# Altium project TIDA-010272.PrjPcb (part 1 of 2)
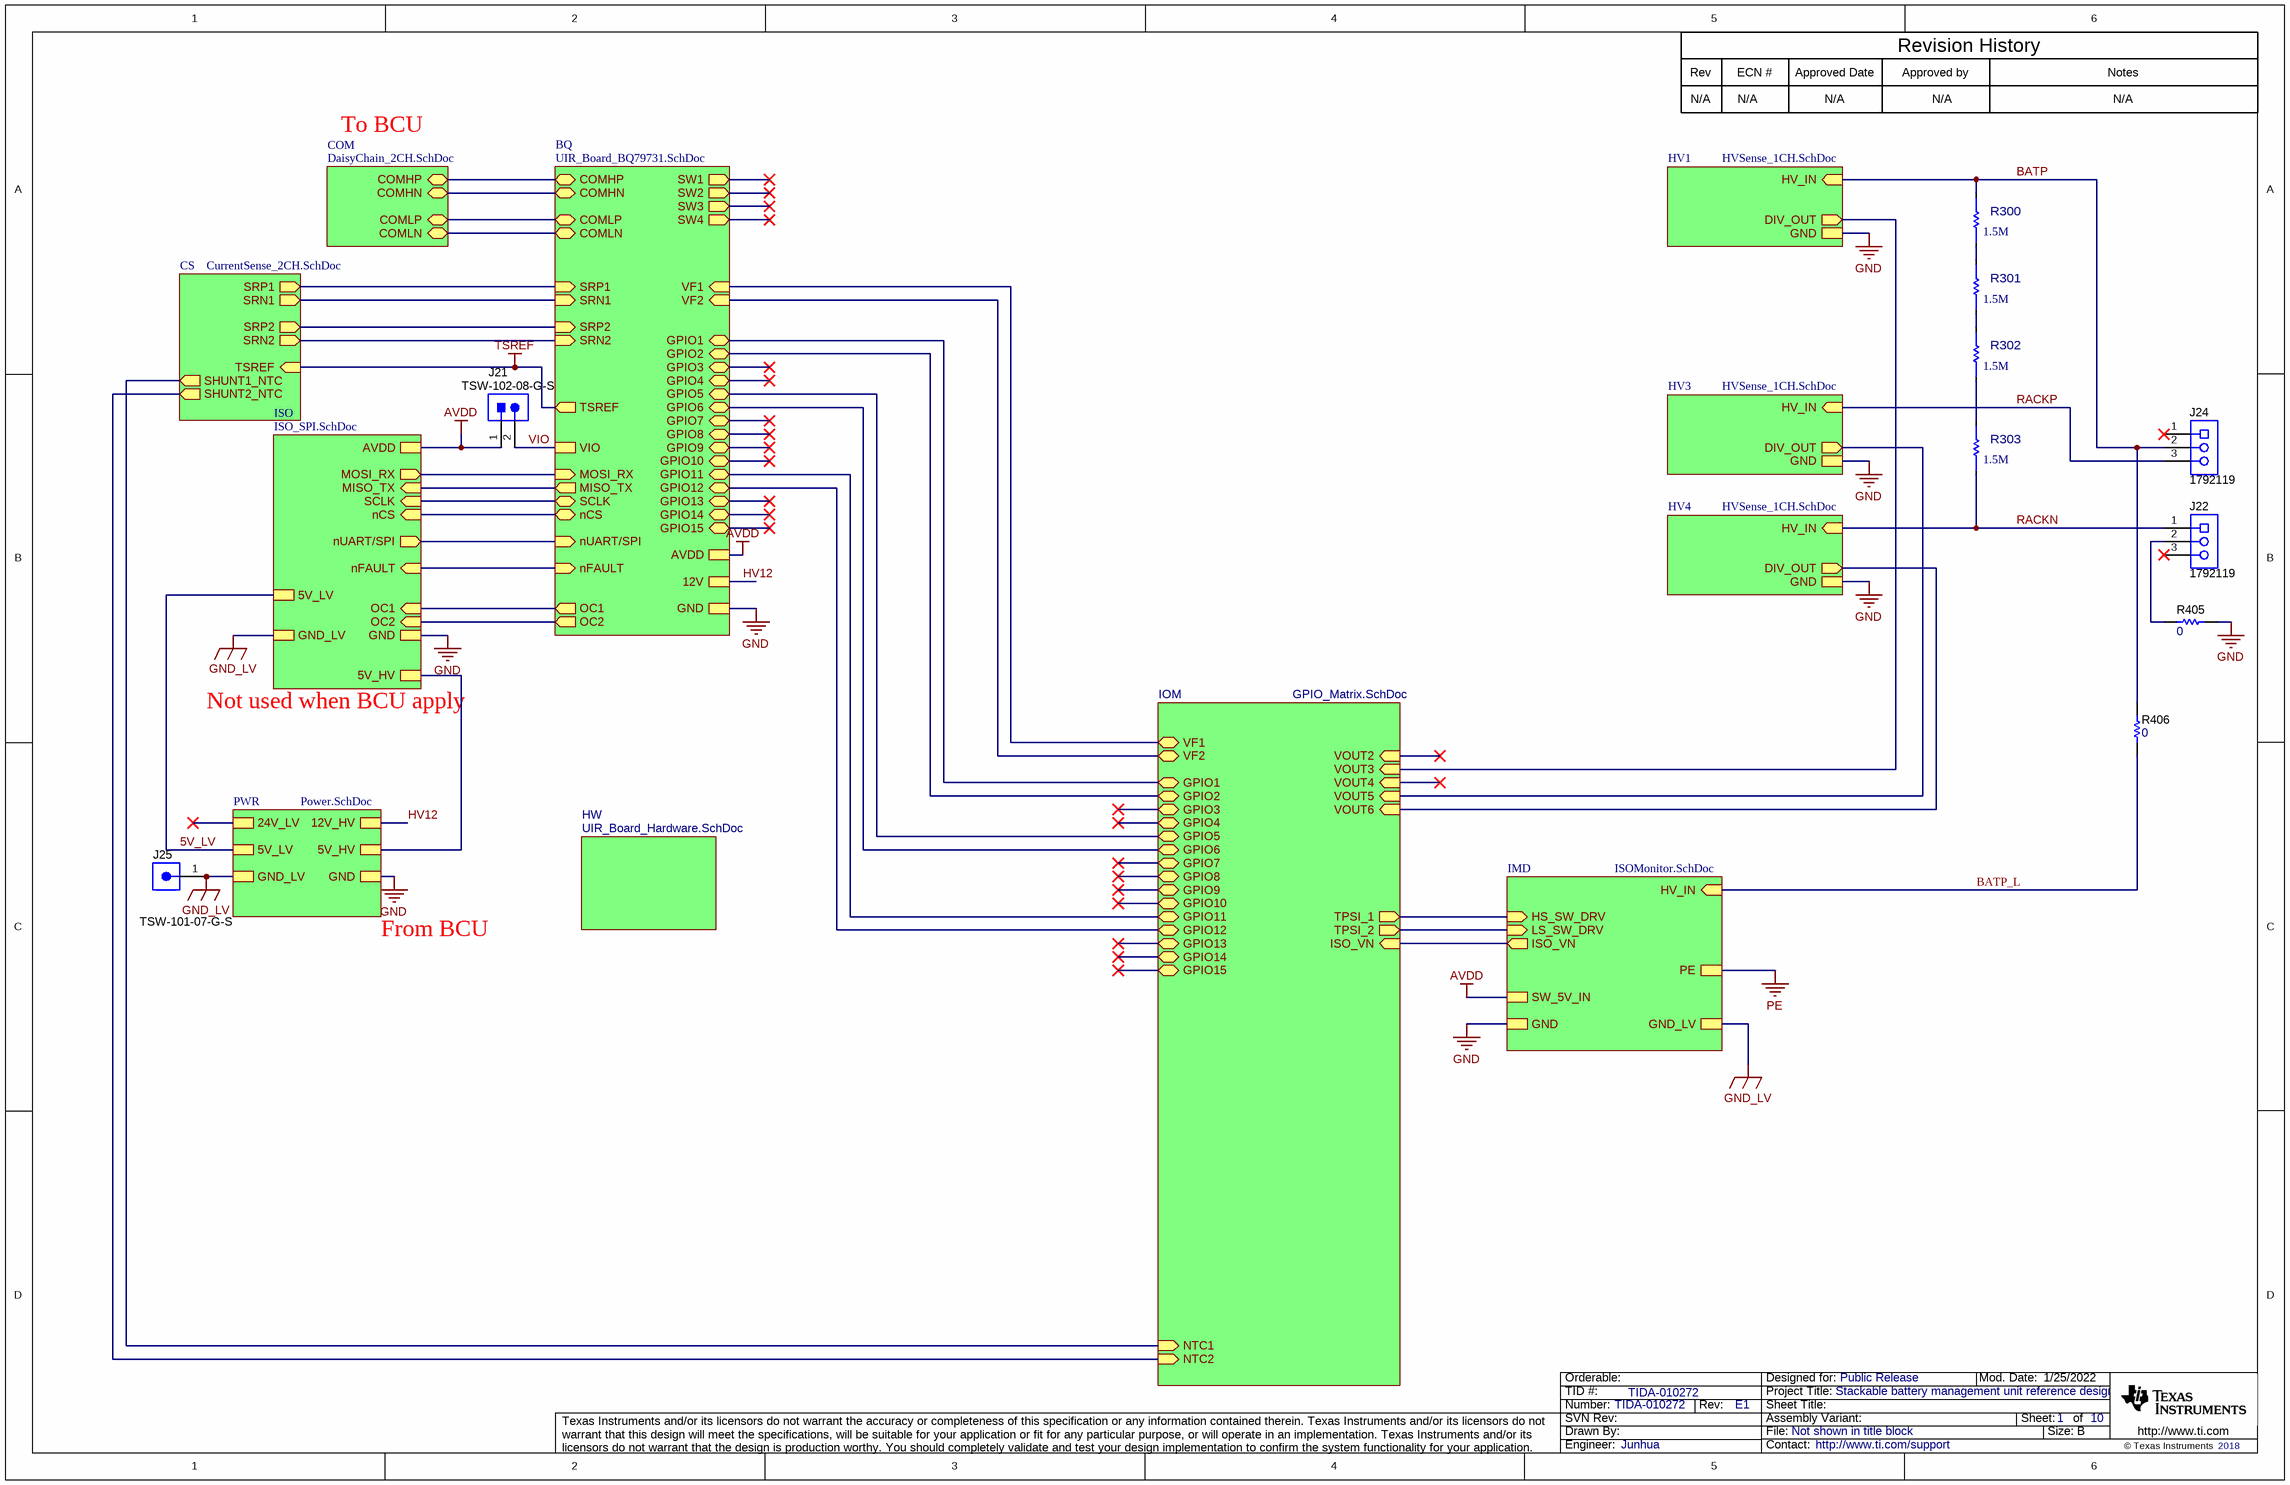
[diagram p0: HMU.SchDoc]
CopyrightYear: 2018; Orderable: N/A; PCB_Layout: Junhua; PCB_Rev: E1; PRJ_Customer: Public Release; PRJ_Engineer: Junhua; PRJ_Number: TIDA-010272; PRJ_Title: Stackable battery management unit reference design; SCH_Rev: E1; TechSupport: http://www.ti.com/support; TID: TIDA-010272
10 sheets, 311 parts. Net scope: hierarchical (ports join the sheet entries above them; power ports are global).
Board file: HMU.PcbDoc
Sheets:
  HMU.SchDoc
    BQ = UIR_Board_BQ79731.SchDoc
    COM = DaisyChain_2CH.SchDoc
    CS = CurrentSense_2CH.SchDoc
    HV1 = HVSense_1CH.SchDoc
    HV3 = HVSense_1CH.SchDoc
    IOM = GPIO_Matrix.SchDoc
    HV4 = HVSense_1CH.SchDoc
    ISO = ISO_SPI.SchDoc
    PWR = Power.SchDoc
    HW = UIR_Board_Hardware.SchDoc
    IMD = ISOMonitor.SchDoc

## Sheet HMU.SchDoc
size 431 x 279 mm; Date: Not shown in title block; ApprovedBy: Not shown in title block; CheckedBy: Not shown in title block; Author: Not shown in title block; CompanyName: Not shown in title block; Engineer: Not shown in title block; Organization: Not shown in title block; Address1: Not shown in title block; Address2: Not shown in title block; Address3: Not shown in title block; Address4: Not shown in title block; DocumentNumber: 1; Revision: Use project parameter SCH_Rev; SheetNumber: 1; SheetTotal: 10; PageSetup: Record=PageOptions¦CenterHorizontal=True¦CenterVertical=True¦PrintScale=1.00¦XCorrection=1.00¦YCorrection=1.00¦PrintKind=0¦BorderSize=5000000¦LeftOffset=0¦BottomOffset=0¦Orientation=2¦PaperLength=1000¦PaperWidth=1000¦Scale=100¦PaperSource=15¦PrintQuality=600¦MediaType=1¦DitherType=10¦PaperKind=Letter¦PrintScaleMode=1

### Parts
J21  TSW-102-08-G-S  [Samtec_TSW-102-08-x-S]
J22  1792119  [Phoenix_1792119]
J24  1792119  [Phoenix_1792119]
J25  TSW-101-07-G-S  [TSW-101-07-G-S]
R300  value 1.5M  [FP-CHV1206-FX-1504ELF_1206-MFG]  (hidden comment: CHV1206-FX-1504ELF)
R301  value 1.5M  [FP-CHV1206-FX-1504ELF_1206-MFG]  (hidden comment: CHV1206-FX-1504ELF)
R302  value 1.5M  [FP-CHV1206-FX-1504ELF_1206-MFG]  (hidden comment: CHV1206-FX-1504ELF)
R303  value 1.5M  [FP-CHV1206-FX-1504ELF_1206-MFG]  (hidden comment: CHV1206-FX-1504ELF)
R405  ValueDisplayed: 0  [0603]  (hidden comment: CRCW06030000Z0EA)
R406  ValueDisplayed: 0  [0603]  (hidden comment: CRCW06030000Z0EA)

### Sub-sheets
BQ = UIR_Board_BQ79731.SchDoc: COMHP (bidir), COMHN (bidir), COMLP (bidir), COMLN (bidir), SW1 (out), SW2 (out), SW3 (out), SW4 (out), OC1 (out), OC2 (out), SRN1 (in), SRN2 (in), SRP1 (in), SRP2 (in), TSREF (out), VIO, MOSI_RX (in), MISO_TX (out), nCS (bidir), SCLK (bidir), nUART/SPI (in), nFAULT (in), VF1 (in), VF2 (in), GPIO1 (bidir), GPIO2 (bidir), GPIO3 (bidir), GPIO4 (bidir), GPIO5 (bidir), GPIO6 (bidir), GPIO7 (bidir), GPIO8 (bidir), GPIO9 (bidir), GPIO10 (bidir), GPIO11 (bidir), GPIO12 (bidir), GPIO13 (bidir), GPIO14 (bidir), GPIO15 (bidir), AVDD, 12V, GND
COM = DaisyChain_2CH.SchDoc: COMHP (bidir), COMHN (bidir), COMLP (bidir), COMLN (bidir)
CS = CurrentSense_2CH.SchDoc: SRN1 (out), SRN2 (out), SRP1 (out), SRP2 (out), SHUNT1_NTC (out), SHUNT2_NTC (out), TSREF (in)
HV1 = HVSense_1CH.SchDoc: HV_IN (in), DIV_OUT (out), GND
HV3 = HVSense_1CH.SchDoc: HV_IN (in), DIV_OUT (out), GND
HV4 = HVSense_1CH.SchDoc: HV_IN (in), DIV_OUT (out), GND
HW = UIR_Board_Hardware.SchDoc: no entries
IMD = ISOMonitor.SchDoc: HV_IN (in), HS_SW_DRV (in), LS_SW_DRV (in), SW_5V_IN, GND_LV, GND, ISO_VN (out), PE
IOM = GPIO_Matrix.SchDoc: GPIO1 (bidir), GPIO2 (bidir), GPIO3 (bidir), GPIO4 (bidir), GPIO5 (bidir), GPIO6 (bidir), GPIO7 (bidir), GPIO8 (bidir), GPIO9 (bidir), GPIO10 (bidir), GPIO11 (bidir), GPIO12 (bidir), GPIO13 (bidir), GPIO14 (bidir), GPIO15 (bidir), VOUT6 (in), VOUT2 (in), VOUT3 (in), VOUT4 (in), VOUT5 (in), ISO_VN (in), TPSI_1 (out), TPSI_2 (out), NTC2 (in), NTC1 (in), VF1 (bidir), VF2 (bidir)
ISO = ISO_SPI.SchDoc: AVDD, MOSI_RX (out), MISO_TX (in), nCS (in), SCLK (in), nUART/SPI (out), nFAULT (in), OC1 (in), OC2 (in), GND, 5V_LV, GND_LV, 5V_HV
PWR = Power.SchDoc: GND_LV, 24V_LV, 12V_HV, 5V_LV, GND, 5V_HV

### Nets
AVDD: J21.1 ; sheet BQ/AVDD, sheet ISO/AVDD, sheet IMD/SW_5V_IN
GND: R405.2 ; sheet BQ/GND, sheet HV1/GND, sheet HV3/GND, sheet HV4/GND, sheet ISO/GND, sheet PWR/GND, sheet IMD/GND
GND_LV: J25.1 ; sheet ISO/GND_LV, sheet PWR/GND_LV, sheet IMD/GND_LV
HV12: sheet BQ/12V, sheet PWR/12V_HV
TSREF: sheet BQ/TSREF, sheet CS/TSREF
VIO: J21.2 ; sheet BQ/VIO
5V_HV: sheet ISO/5V_HV, sheet PWR/5V_HV
5V_LV: sheet ISO/5V_LV, sheet PWR/5V_LV
BATP: J24.2 R300.2 R406.2 ; sheet HV1/HV_IN
BATP_L: R406.1 ; sheet IMD/HV_IN
COMHN: sheet BQ/COMHN, sheet COM/COMHN
COMHP: sheet BQ/COMHP, sheet COM/COMHP
COMLN: sheet BQ/COMLN, sheet COM/COMLN
COMLP: sheet BQ/COMLP, sheet COM/COMLP
DIV_OUT: sheet HV1/DIV_OUT, sheet IOM/VOUT3
DIV_OUT: sheet HV3/DIV_OUT, sheet IOM/VOUT5  [a separate net that carries the same name]
DIV_OUT: sheet IOM/VOUT6, sheet HV4/DIV_OUT  [a separate net that carries the same name]
GPIO1: sheet BQ/GPIO1, sheet IOM/GPIO1
GPIO2: sheet BQ/GPIO2, sheet IOM/GPIO2
GPIO5: sheet BQ/GPIO5, sheet IOM/GPIO5
GPIO6: sheet BQ/GPIO6, sheet IOM/GPIO6
GPIO11: sheet BQ/GPIO11, sheet IOM/GPIO11
GPIO12: sheet BQ/GPIO12, sheet IOM/GPIO12
HS_SW_DRV: sheet IOM/TPSI_1, sheet IMD/HS_SW_DRV
ISO_VN: sheet IOM/ISO_VN, sheet IMD/ISO_VN
LS_SW_DRV: sheet IOM/TPSI_2, sheet IMD/LS_SW_DRV
MISO_TX: sheet BQ/MISO_TX, sheet ISO/MISO_TX
MOSI_RX: sheet BQ/MOSI_RX, sheet ISO/MOSI_RX
nCS: sheet BQ/nCS, sheet ISO/nCS
nFAULT: sheet BQ/nFAULT, sheet ISO/nFAULT
NTC1: sheet CS/SHUNT1_NTC, sheet IOM/NTC1
NTC2: sheet CS/SHUNT2_NTC, sheet IOM/NTC2
nUART/SPI: sheet BQ/nUART/SPI, sheet ISO/nUART/SPI
OC1: sheet BQ/OC1, sheet ISO/OC1
OC2: sheet BQ/OC2, sheet ISO/OC2
RACKN: J22.1 R303.1 ; sheet HV4/HV_IN
RACKP: J24.3 ; sheet HV3/HV_IN
SCLK: sheet BQ/SCLK, sheet ISO/SCLK
SRN1: sheet BQ/SRN1, sheet CS/SRN1
SRN2: sheet BQ/SRN2, sheet CS/SRN2
SRP1: sheet BQ/SRP1, sheet CS/SRP1
SRP2: sheet BQ/SRP2, sheet CS/SRP2
VF1: sheet BQ/VF1, sheet IOM/VF1
VF2: sheet BQ/VF2, sheet IOM/VF2
NetJ22_2: J22.2 R405.1
NetR300_1: R300.1 R301.2
NetR301_1: R301.1 R302.2
NetR302_1: R302.1 R303.2

Not connected (* = marked no-connect by the designer): J22 3*; J24 1*

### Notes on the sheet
- Rev
- N/A
- ECN #
- Approved Date
- Approved by
- Revision History
- Notes
- To BCU
- Not used when BCU apply
- From BCU

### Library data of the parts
J21 = CMP-0077643-1: Header, 2.54mm, 2x1, Gold, TH; Manufacturer: Samtec; Pitch_mm: 2.54; Gender: Male; Cert_CSA: Y; Current_A: 5.7A; Voltage_V: 550V; Row_Count: 1
J22 J24 = CMP-0055525-1: Terminal Block, 7.5mm, 3x1, R/A, TH; Manufacturer: Phoenix Contact; Cert_VDE: Y; CNHeader: FALSE; Current_A: 41A; Gender: Female; Voltage_V: 1kV; Row_Count: 1; Pitch_mm: 7.5; CT: TRUE
J25 = CMP-0075403-1: Header, 100mil, 1pos, Gold, TH; Manufacturer: Samtec; Pitch_mm: 2.54; Cert_VDE: N; Gender: Male; Cert_CSA: Y; Voltage_V: 550V; Green_REACh: Passed; Current_A: 6.3A; CT: False; Green_Lifecycle: Active; Row_Count: 1; CNHeader: True
R300-R303 = CMP-0120473-1: Thick Film High Voltage Chip Resistors 1206 1.5MOhm ±1% ±100ppm/°C; Manufacturer: Bourns; AEC Qualified: No; Power_W: 250mW; SizeZ_mm: 0.65mm; VDC_V: 800V
R405 R406 = CMP-0025697-4: RES, 0, 5%, 0.1 W, AEC-Q200 Grade 0, 0603; Manufacturer: Vishay-Dale; Power_W: 100mW; TempCo: 200 ppm/C; Value_Code: 0000; Value: 0; EIA_Code: E24; SizeX_mm: 1.6; SizeY_mm: 0.8; SizeZ_mm: 1; Value2: 0.1W; SizeArea_mm2: 1.28; AEC Qualified: Y; VDC_V: 75V; AEC Category: Q200

## Sheet UIR_Board_BQ79731.SchDoc
size 431 x 279 mm; SheetNumber: 7; SheetTotal: 10
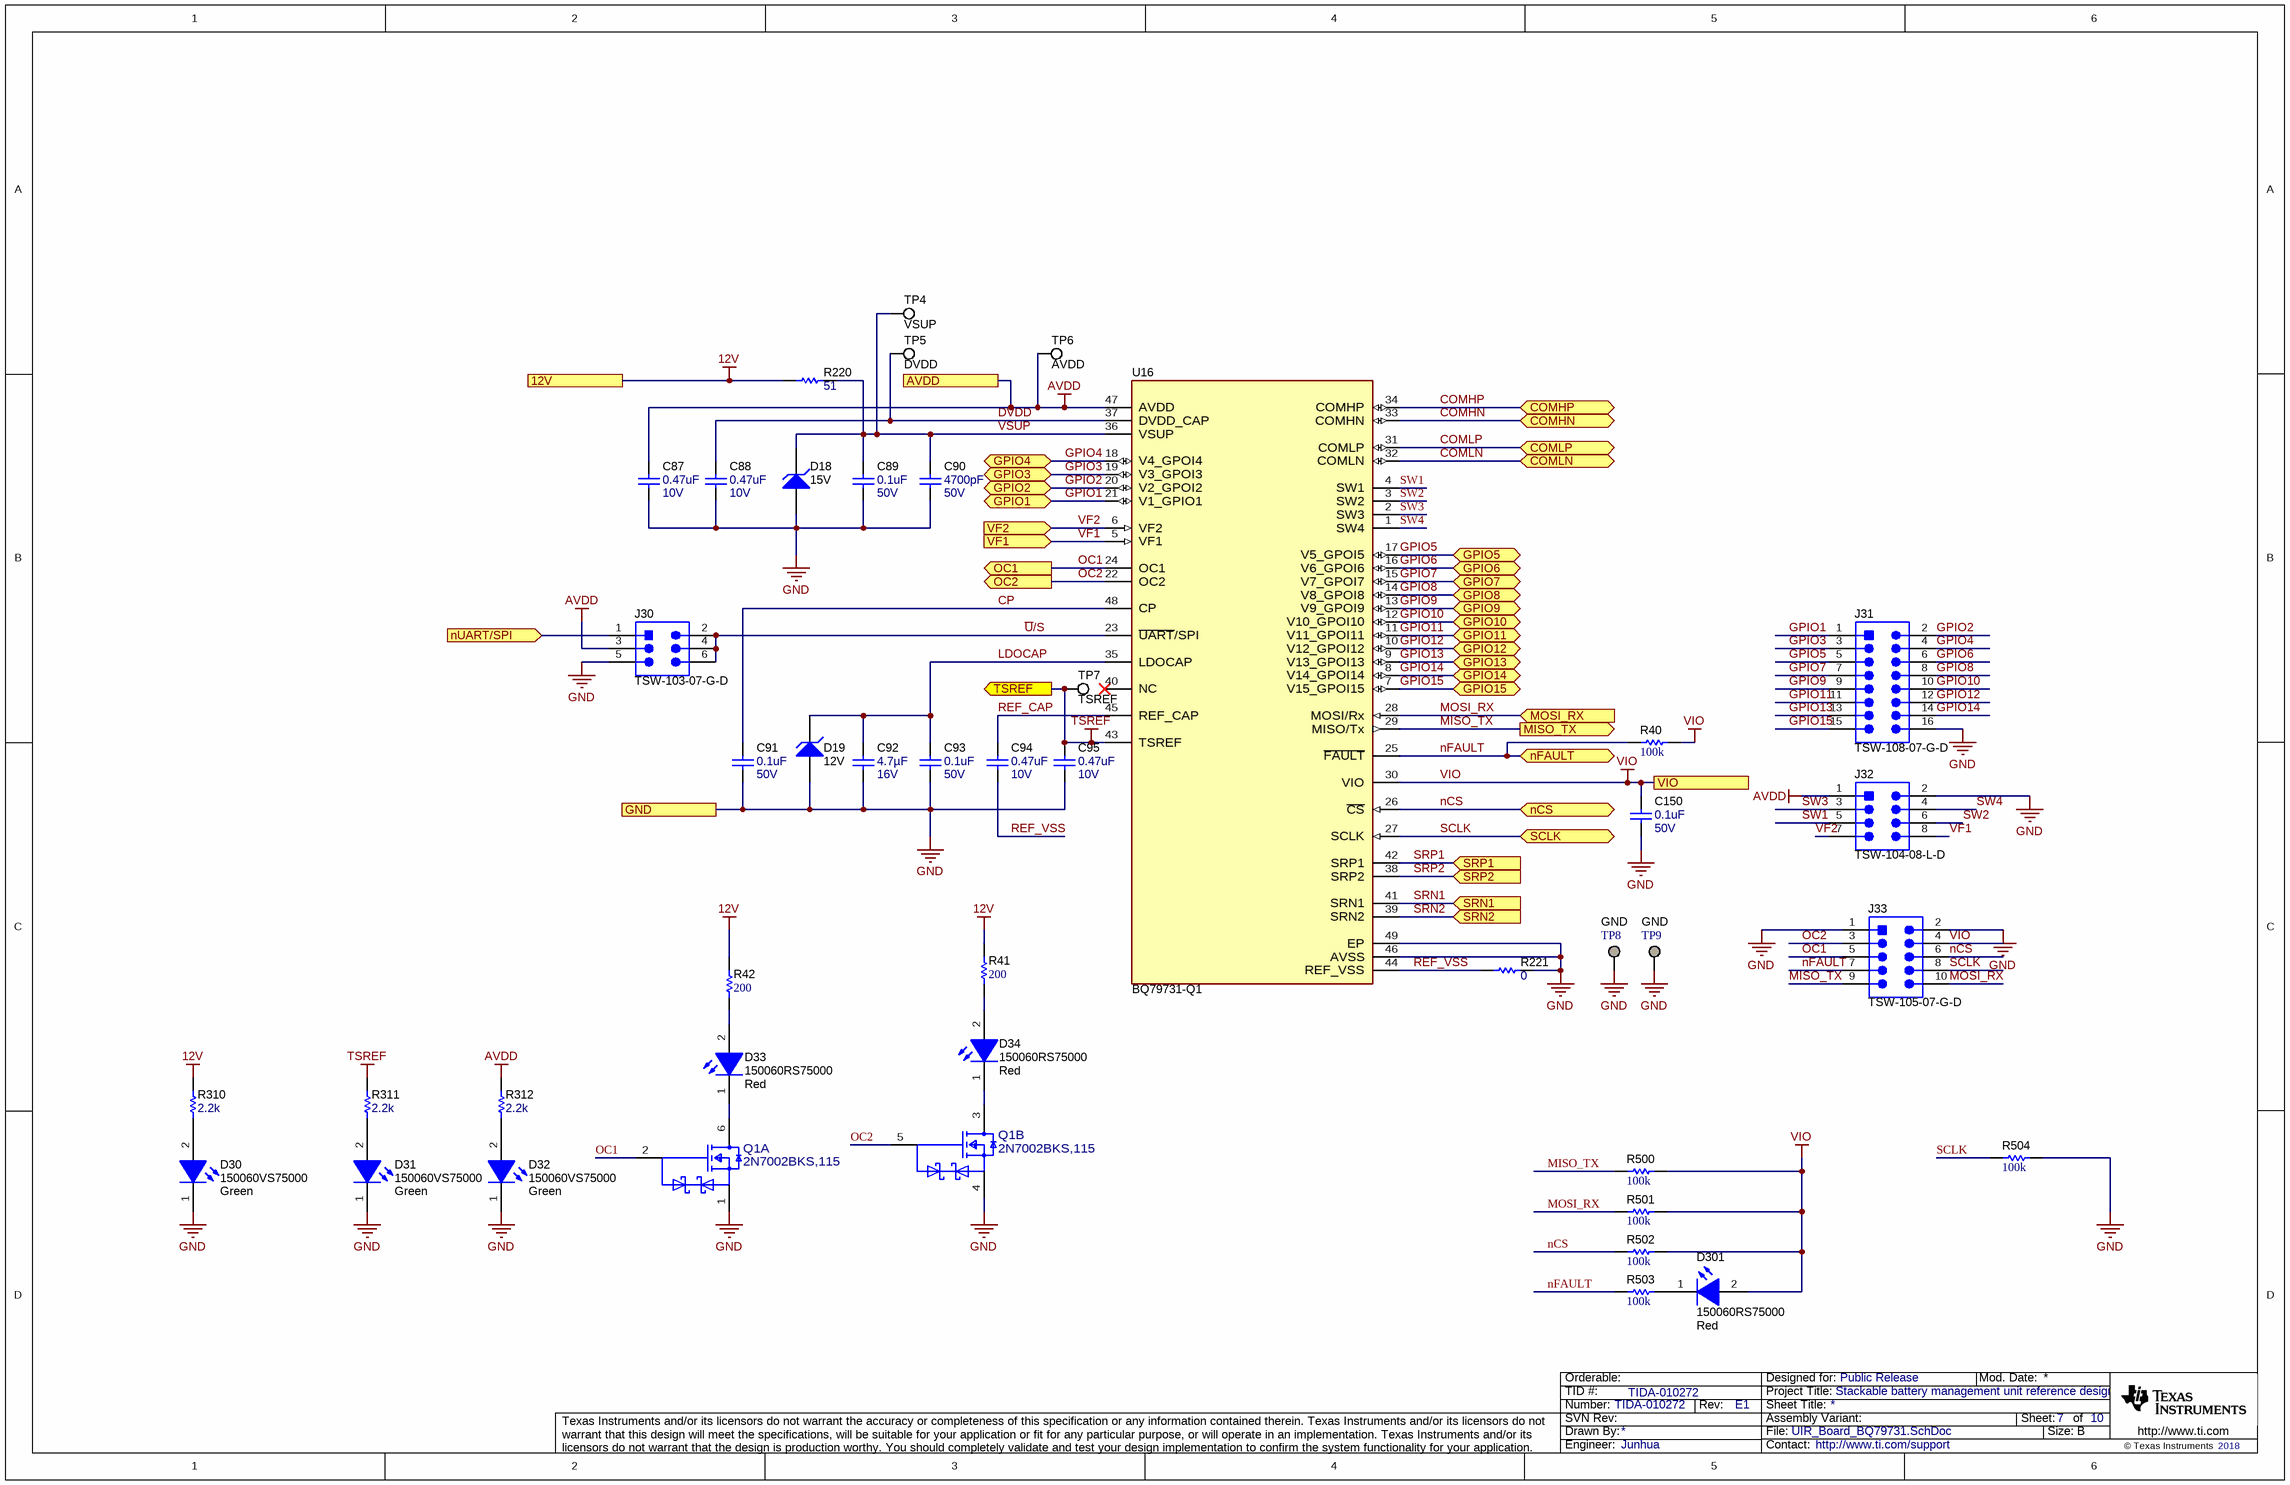
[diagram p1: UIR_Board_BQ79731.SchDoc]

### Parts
C87  VDC_V: 10V  ValueDisplayed: 0.47uF  [0402]  (hidden comment: GRM155R61A474KE15D)
C88  VDC_V: 10V  ValueDisplayed: 0.47uF  [0402]  (hidden comment: GRM155R61A474KE15D)
C89  VDC_V: 50V  ValueDisplayed: 0.1uF  [0402]  (hidden comment: GCM155R71H104KE02D)
C90  VDC_V: 50V  ValueDisplayed: 4700pF  [0402]  (hidden comment: GCM155R71H472KA37D)
C91  VDC_V: 50V  ValueDisplayed: 0.1uF  [0402]  (hidden comment: GCM155R71H104KE02D)
C92  VDC_V: 16V  ValueDisplayed: 4.7µF  [0603]  (hidden comment: GRT188R61C475KE13D)
C93  VDC_V: 50V  ValueDisplayed: 0.1uF  [0402]  (hidden comment: GCM155R71H104KE02D)
C94  VDC_V: 10V  ValueDisplayed: 0.47uF  [0402]  (hidden comment: GRM155R61A474KE15D)
C95  VDC_V: 10V  ValueDisplayed: 0.47uF  [0402]  (hidden comment: GRM155R61A474KE15D)
C150  VDC_V: 50V  ValueDisplayed: 0.1uF  [0402]  (hidden comment: GCM155R71H104KE02D)
D18  value 15V  [SOD-123]  (hidden comment: MMSZ4702-HE3-08)
D19  value 12V  [SOD-123]  (hidden comment: BZT52B12-E3-08)
D30  150060VS75000  value Green  [WL-SMCW_GREEN]
D31  150060VS75000  value Green  [WL-SMCW_GREEN]
D32  150060VS75000  value Green  [WL-SMCW_GREEN]
D33  150060RS75000  value Red  [WL-SMCW_RED]
D34  150060RS75000  value Red  [WL-SMCW_RED]
D301  150060RS75000  value Red  [WL-SMCW_RED]
J30  TSW-103-07-G-D  [TSW-103-07-G-D]
J31  TSW-108-07-G-D  [TSW-108-07-G-D]
J32  TSW-104-08-L-D  [Samtec_TSW-104-08-x-D]
J33  TSW-105-07-G-D  [TSW-105-07-G-D]
Q1  2N7002BKS,115  [FP-2N7002BKS,115_SOT363-MFG]  (parts A,B of 2)
R40  ValueDisplayed: 100k  [0603]  (hidden comment: CRCW0603100KJNEA)
R41  ValueDisplayed: 200  [0603]  (hidden comment: RT0603DRE07200RL)
R42  ValueDisplayed: 200  [0603]  (hidden comment: RT0603DRE07200RL)
R220  ValueDisplayed: 51  [0805_HV]  (hidden comment: CRCW080551R0JNEA)
R221  ValueDisplayed: 0  [0402]  (hidden comment: CRCW04020000Z0ED)
R310  ValueDisplayed: 2.2k  [0603]  (hidden comment: CRCW06032K20JNEA)
R311  ValueDisplayed: 2.2k  [0603]  (hidden comment: CRCW06032K20JNEA)
R312  ValueDisplayed: 2.2k  [0603]  (hidden comment: CRCW06032K20JNEA)
R500  ValueDisplayed: 100k  [0603]  (hidden comment: CRCW0603100KJNEA)
R501  ValueDisplayed: 100k  [0603]  (hidden comment: CRCW0603100KJNEA)
R502  ValueDisplayed: 100k  [0603]  (hidden comment: CRCW0603100KJNEA)
R503  ValueDisplayed: 100k  [0603]  (hidden comment: CRCW0603100KJNEA)
R504  ValueDisplayed: 100k  [0603]  (hidden comment: CRCW0603100KJNEA)
TP4  VSUP  [Keystone5012]
TP5  DVDD  [Keystone5012]
TP6  AVDD  [Keystone5012]
TP7  TSREF  [Keystone5012]
TP8  GND  [Keystone1598-2]
TP9  GND  [Keystone1598-2]
U16  BQ79731-Q1  [PHP0048E-MFG]

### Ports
12V, AVDD, COMHN (bidir), COMHP (bidir), COMLN (bidir), COMLP (bidir), GND, GPIO1 (bidir), GPIO2 (bidir), GPIO3 (bidir), GPIO4 (bidir), GPIO5 (bidir), GPIO6 (bidir), GPIO7 (bidir), GPIO8 (bidir), GPIO9 (bidir), GPIO10 (bidir), GPIO11 (bidir), GPIO12 (bidir), GPIO13 (bidir), GPIO14 (bidir), GPIO15 (bidir), MISO_TX (out), MOSI_RX (in), nCS (bidir), nFAULT (bidir), nUART/SPI (in), OC1 (out), OC2 (out), SCLK (bidir), SRN1 (in), SRN2 (in), SRP1 (in), SRP2 (in), TSREF (out), VF1 (in), VF2 (in), VIO

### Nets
12V: R41.2 R42.2 R220.1 R310.2 ; port 12V  [project net HV12]
AVDD: C87.1 J30.3 J32.1 R312.2 TP6.1 U16.47(AVDD) ; port AVDD
GND: C87.2 C88.2 C89.2 C90.2 C91.2 C92.2 C93.2 C95.2 C150.2 D18.2(A) D19.2(A) D30.1(K) D31.1(K) D32.1(K) J30.5 J31.16 J32.2 J33.1 J33.2 Q1.1(S1) Q1.4(S2) R221.2 R504.2 TP8.1 TP9.1 U16.46(AVSS) U16.49(EP) ; port GND
TSREF: C95.1 R311.2 TP7.1 U16.43(TSREF) ; port TSREF
VIO: C150.1 D301.2(A) J33.4 R40.1 R500.2 R501.2 R502.2 U16.30(VIO) ; port VIO
COMHN: U16.33(COMHN) ; port COMHN
COMHP: U16.34(COMHP) ; port COMHP
COMLN: U16.32(COMLN) ; port COMLN
COMLP: U16.31(COMLP) ; port COMLP
CP: C91.1 U16.48(CP)
DVDD: C88.1 TP5.1 U16.37(DVDD_CAP)
GPIO1: J31.1 U16.21(V1_GPIO1) ; port GPIO1
GPIO2: J31.2 U16.20(V2_GPOI2) ; port GPIO2
GPIO3: J31.3 U16.19(V3_GPOI3) ; port GPIO3
GPIO4: J31.4 U16.18(V4_GPOI4) ; port GPIO4
GPIO5: J31.5 U16.17(V5_GPOI5) ; port GPIO5
GPIO6: J31.6 U16.16(V6_GPOI6) ; port GPIO6
GPIO7: J31.7 U16.15(V7_GPOI7) ; port GPIO7
GPIO8: J31.8 U16.14(V8_GPOI8) ; port GPIO8
GPIO9: J31.9 U16.13(V9_GPOI9) ; port GPIO9
GPIO10: J31.10 U16.12(V10_GPOI10) ; port GPIO10
GPIO11: J31.11 U16.11(V11_GPOI11) ; port GPIO11
GPIO12: J31.12 U16.10(V12_GPOI12) ; port GPIO12
GPIO13: J31.13 U16.9(V13_GPOI13) ; port GPIO13
GPIO14: J31.14 U16.8(V14_GPOI14) ; port GPIO14
GPIO15: J31.15 U16.7(V15_GPOI15) ; port GPIO15
LDOCAP: C92.1 C93.1 D19.1(K) U16.35(LDOCAP)
MISO_TX: J33.9 R500.1 U16.29(MISO/Tx) ; port MISO_TX
MOSI_RX: J33.10 R501.1 U16.28(MOSI/Rx) ; port MOSI_RX
nCS: J33.6 R502.1 U16.26(~{CS}) ; port nCS
nFAULT: J33.7 R40.2 R503.1 U16.25(~{FAULT}) ; port nFAULT
nUART/SPI: J30.1 ; port nUART/SPI
OC1: J33.5 Q1.2(G1) U16.24(OC1) ; port OC1
OC2: J33.3 Q1.5(G2) U16.22(OC2) ; port OC2
REF_CAP: C94.1 U16.45(REF_CAP)
REF_VSS: C94.2 R221.1 U16.44(REF_VSS)
SCLK: J33.8 R504.1 U16.27(SCLK) ; port SCLK
SRN1: U16.41(SRN1) ; port SRN1
SRN2: U16.39(SRN2) ; port SRN2
SRP1: U16.42(SRP1) ; port SRP1
SRP2: U16.38(SRP2) ; port SRP2
SW1: J32.5 U16.4(SW1)
SW2: J32.6 U16.3(SW2)
SW3: J32.3 U16.2(SW3)
SW4: J32.4 U16.1(SW4)
~{U}/S: J30.2 J30.4 J30.6 U16.23(~{UART}/SPI)
VF1: J32.8 U16.5(VF1) ; port VF1
VF2: J32.7 U16.6(VF2) ; port VF2
VSUP: C89.1 C90.1 D18.1(K) R220.2 TP4.1 U16.36(VSUP)
NetD30_2: D30.2(A) R310.1
NetD31_2: D31.2(A) R311.1
NetD32_2: D32.2(A) R312.1
NetD33_1: D33.1(K) Q1.6(D1)
NetD33_2: D33.2(A) R42.1
NetD34_1: D34.1(K) Q1.3(D2)
NetD34_2: D34.2(A) R41.1
NetD301_1: D301.1(K) R503.2

Not connected (* = marked no-connect by the designer): U16 40(NC)*

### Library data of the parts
C87 C88 C94 C95 = CMP-0006580-2: CAP, CERM, 0.47 uF, 10 V, +/- 10%, X5R, 0402; Manufacturer: MuRata; TaMin_C: -55°C; Polarized: N; SizeAreaWB_mm2: 3; Value1: Unknown; U/M: EA; Value: 0.47uF; TaMax_C: 85°C; SizeZ_mm: 0.6; SizeX_mm: 1; SizeY_mm: 0.5; Cap_F: 470nF; AEC Category: Q200
C89 C91 C93 C150 = CMP-0006356-2: CAP, CERM, 0.1 uF, 50 V, +/- 10%, X7R, AEC-Q200 Grade 1, 0402; Manufacturer: MuRata; TaMin_C: -55°C; Polarized: N; SizeAreaWB_mm2: 3; Value1: Unknown; U/M: EA; Value: 0.1uF; TaMax_C: 125°C; SizeZ_mm: 0.6; SizeX_mm: 1; SizeY_mm: 0.5; AEC Qualified: Y; Cap_F: 100nF; AEC Category: Q200
C90 = CMP-0006361-2: CAP, CERM, 4700 pF, 50 V, +/- 10%, X7R, AEC-Q200 Grade 1, 0402; Manufacturer: MuRata; TaMin_C: -55°C; Polarized: N; SizeAreaWB_mm2: 3; Value1: Unknown; U/M: EA; Value: 4700pF; TaMax_C: 125°C; SizeZ_mm: 0.6; SizeX_mm: 1; SizeY_mm: 0.5; AEC Qualified: Y; Cap_F: 4.7nF; AEC Category: Q200
C92 = CMP-0081052-1: CAP, CERM, 4.7 µF, 16 V,+/- 10%, X5R, AEC-Q200 Grade 3, 0603; Manufacturer: MuRata; SizeAreaWB_mm2: 4.68; SizeArea_mm2: 1.28; AEC Qualified: Y; AEC Category: Q200; Value: 4.7uF; TaMax_C: 85°C; SizeZ_mm: 1; AEC Grade: 3; Polarized: N; TaMin_C: -55°C; SizeY_mm: 0.8; U/M: EA; SizeX_mm: 1.6
D18 = CMP-0077575-3: Diode, Zener, 15 V, 500 mW, AEC-Q101, SOD-123; Manufacturer: Vishay-Semiconductor; SizeAreaWB_mm2: 13.095; Power_W: 500mW; AEC Category: Q101; SizeX_mm: 3.85; Value1: 0.5W; SizeZ_mm: 1.35; AEC Qualified: Y; SizeY_mm: 1.7; SizeArea_mm2: 6.545; RJA_CperW: 340
D19 = CMP-0005773-4: Diode, Zener, 12 V, 500 mW, AEC-Q101, SOD-123; Manufacturer: Vishay-Semiconductor; SizeX_mm: 3.85; RJA_CperW: 300; SizeY_mm: 1.7; AEC Qualified: Y; SizeZ_mm: 1.35; Power_W: 500mW; AEC Category: Q101; SizeAreaWB_mm2: 13.095; Value1: 0.5W; SizeArea_mm2: 6.545
D30-D32 = CMP-0002894-2: LED, Green, SMD; Manufacturer: Wurth Elektronik; Type: AlInGaP; Value2: 2V; Io_A: 20mA; Value1: W
D33 D34 D301 = CMP-0002947-3: LED, Red, SMD; Manufacturer: Wurth Elektronik; Value1: 0.072W; Vf_V: 2V; Angle: 140; Tjmax_C: 85°C; Type: AlInGaP; Vr_V: 5V; Io_A: 30mA; Power_TotalModule: 72mW
J30 = CMP-0075406-2: Header, 100mil, 3x2, Gold, TH; Manufacturer: Samtec; Pitch_mm: 2.54; Cert_VDE: N; Gender: Male; Cert_CSA: Y; Voltage_V: 550V; Green_REACh: Passed; Current_A: 6.3A; Green_Lifecycle: Active; Row_Count: 2
J31 = CMP-0075418-1: Header, 100mil, 8x2, Gold, TH; Manufacturer: Samtec; Pitch_mm: 2.54; Cert_VDE: N; Gender: Male; Cert_CSA: Y; Voltage_V: 550V; Green_REACh: Passed; Current_A: 6.3A; CT: False; Green_Lifecycle: Active; Row_Count: 2; CNHeader: True
J32 = CMP-0055596-2: Header, 2.54mm, 4x2, Gold, TH; Manufacturer: Samtec; Current_A: 6.3A; Shrouded: N; Gender: Male; Cert_CSA: Y; Voltage_V: 550V; Row_Count: 2; RowSpacing_mm: 2.54
J33 = CMP-0075410-2: Header, 100mil, 5x2, Gold, TH; Manufacturer: Samtec; Pitch_mm: 2.54; Cert_VDE: N; Gender: Male; Cert_CSA: Y; Voltage_V: 550V; Green_REACh: Passed; Current_A: 6.3A; Green_Lifecycle: Active; Row_Count: 2
Q1 = CMP-0089965-1: Mosfet Array 2 N-Channel (Dual) 60V 300mA 295mW Surface Mount 6-TSSOP; Manufacturer: Nexperia; Pulse Drain Current: 1.2A; Vgs_V: 20V; Typ Forward Diode Voltage: 0.75V; AEC Grade: Grade 0; Rdson45_ohm: 1; Threshold Vgs Max: 2.1V; QgTyp_nC: 0.5nC @ 4.5V; Rthja Max: 370K/W; VdsMax_V: 1.1V; TJmax_C: +150°C; AEC Qualified: Yes; Turn On Delay Time: 5ns; Number Of Channels: 2; ChMode: False; TaMin_C: -55°C; Input Capacitace At Vds: 33pF @ 10V; Turn Off Delay Time: 12ns; SizeZ_mm: 1.1mm; Transconductance: 0.55S
R40 R500-R504 = CMP-0025698-4: RES, 100 k, 5%, 0.1 W, AEC-Q200 Grade 0, 0603; Manufacturer: Vishay-Dale; Power_W: 100mW; TempCo: 200 ppm/C; Value: 100k; EIA_Code: E24; SizeX_mm: 1.6; SizeY_mm: 0.8; SizeZ_mm: 1; Value2: 0.1W; SizeArea_mm2: 1.28; AEC Qualified: Y; VDC_V: 75V; AEC Category: Q200; AEC Grade: 0
R41 R42 = CMP-0024912-2: RES, 200, 0.5%, 0.1 W, 0603; Manufacturer: Yageo America; Power_W: 100mW; TempCo: 50 ppm/C; Value_Code: 200R; U/M: EA; Value: 200; EIA_Code: E192; SizeX_mm: 1.6; SizeY_mm: 0.8; SizeZ_mm: 1; Value2: 0.1W; SizeArea_mm2: 1.28; VDC_V: 75V; AEC Category: Q200
R220 = CMP-0020567-3: RES, 51, 5%, 0.125 W, AEC-Q200 Grade 0, 0805; Manufacturer: Vishay-Dale; Power_W: 125mW; TempCo: 200 ppm/C; Value_Code: 51R0; Value: 51; EIA_Code: E24; SizeX_mm: 2; SizeY_mm: 1.25; SizeZ_mm: 1.45; Value2: 0.125W; SizeArea_mm2: 2.5; AEC Qualified: Y; VDC_V: 150V; AEC Category: Q200; AEC Grade: 0
R221 = CMP-0026822-3: RES, 0, 5%, 0.063 W, AEC-Q200 Grade 0, 0402; Manufacturer: Vishay-Dale; Power_W: 63mW; TempCo: 200 ppm/C; Value_Code: 0000; Value: 0; EIA_Code: E24; SizeX_mm: 1; SizeY_mm: 0.5; SizeZ_mm: 0.6; Value2: 0.063W; AEC Qualified: Y; VDC_V: 50V; AEC Category: Q200
R310-R312 = CMP-0025769-4: RES, 2.2 k, 5%, 0.1 W, AEC-Q200 Grade 0, 0603; Manufacturer: Vishay-Dale; Power_W: 100mW; TempCo: 200 ppm/C; Value_Code: 2k20; Value: 2.2k; EIA_Code: E24; SizeX_mm: 1.6; SizeY_mm: 0.8; SizeZ_mm: 1; Value2: 0.1W; SizeArea_mm2: 1.28; AEC Qualified: Y; VDC_V: 75V; AEC Category: Q200; AEC Grade: 0
TP4-TP7 = CMP-0055149-1: Test Point, Multipurpose, White, TH; PartNumber: 5012; Manufacturer: Keystone; ContactFinish: Silver; CNHeader: FALSE; Green_Lifecycle: Active; Green_REACh: Passed; CT: TRUE
TP8 TP9 = CMP-0055121-1: Terminal, Turret, TH, Triple; Manufacturer: Keystone; PartNumber: 1598-2; CT: FALSE; Green_REACh: Passed; CompType: Turret Terminal; Green_Lifecycle: Active
U16 = CMP-0093215-2: Functional Safety-Compliant Automotive UIR sensor for Battery Junction Box (BJB) and other High Voltge and Current sensing; Manufacturer: Texas Instruments; Number Of Outputs: 4; Nominal Supply Current: 10mA; AEC Category: Q200; TaMin_C: -40°C; AEC Qualified: Yes; Min Supply Voltage: 6V; AEC Grade: Grade 1; Max Supply Voltage: 18V; CompType: IC; TaMax_C: +125°C; Standoff Height: 0.05mm; SizeZ_mm: 1.2mm; TJmax_C: +150°C

## Sheet DaisyChain_2CH.SchDoc
size 431 x 279 mm; SheetNumber: 5; SheetTotal: 10
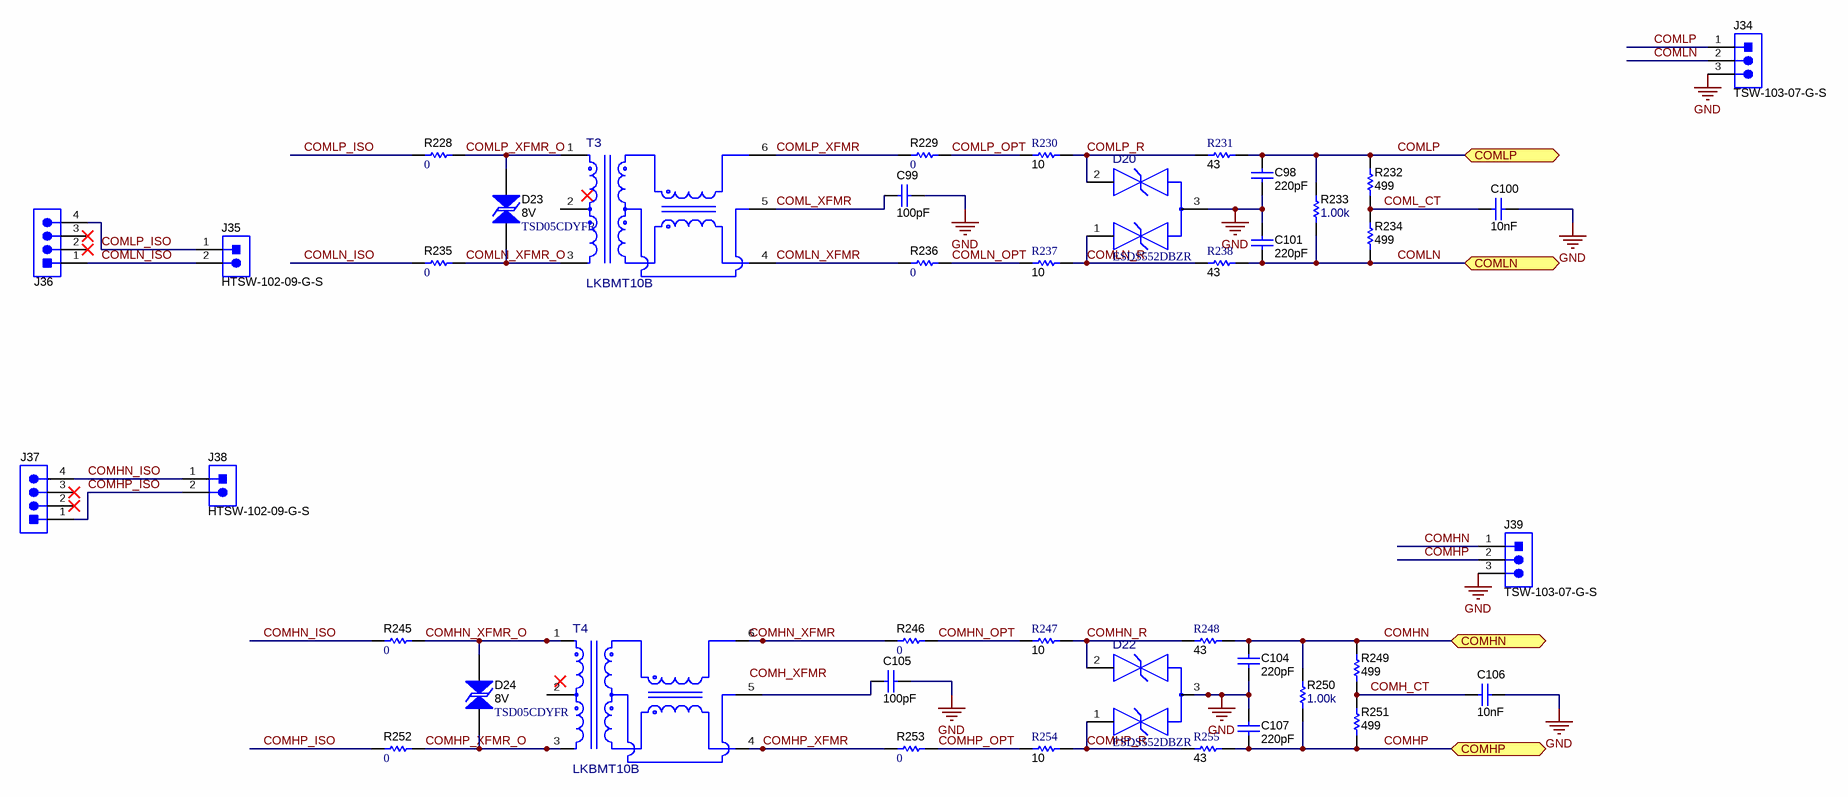
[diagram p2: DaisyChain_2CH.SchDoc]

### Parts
C98  Cap_F: 220pF  [0603]  (hidden comment: CL10B221JB8NNNC)
C99  ValueDisplayed: 100pF  [0603]  (hidden comment: GCM1885C1H101JA16J)
C100  Cap_F: 10nF  [0603]  (hidden comment: CL10B103KB8NCNC)
C101  Cap_F: 220pF  [0603]  (hidden comment: CL10B221JB8NNNC)
C104  Cap_F: 220pF  [0603]  (hidden comment: CL10B221JB8NNNC)
C105  ValueDisplayed: 100pF  [0603]  (hidden comment: GCM1885C1H101JA16J)
C106  Cap_F: 10nF  [0603]  (hidden comment: CL10B103KB8NCNC)
C107  Cap_F: 220pF  [0603]  (hidden comment: CL10B221JB8NNNC)
D20  ESDS552DBZR  [DBZ0003A-MFG]
D22  ESDS552DBZR  [DBZ0003A-MFG]
D23  value 8V  PartNumber: TSD05CDYFR  [SOD-323-Bi]  (hidden comment: CDSOD323-T08SC)
D24  value 8V  PartNumber: TSD05CDYFR  [SOD-323-Bi]  (hidden comment: CDSOD323-T08SC)
J34  TSW-103-07-G-S  [TSW-103-07-G-S]
J35  HTSW-102-09-G-S  [Samtec_HTSW-102-09-x-S]
J36  70551-0038  [Molex_70551-0038]  (value not drawn)
J37  70551-0038  [Molex_70551-0038]  (value not drawn)
J38  HTSW-102-09-G-S  [Samtec_HTSW-102-09-x-S]
J39  TSW-103-07-G-S  [TSW-103-07-G-S]
R228  ValueDisplayed: 0  [0603]  (hidden comment: RC0603JR-070RL)
R229  ValueDisplayed: 0  [0603]  (hidden comment: RC0603JR-070RL)
R230  ValueDisplayed: 10  [0603]  (hidden comment: CRCW060310R0JNEA)
R231  ValueDisplayed: 43  [0603]  (hidden comment: CRCW060343R0JNEA)
R232  ValueDisplayed: 499  [0603]  (hidden comment: RC0603FR-07499RL)
R233  ValueDisplayed: 1.00k  [0603]  (hidden comment: CRCW06031K00FKEA)
R234  ValueDisplayed: 499  [0603]  (hidden comment: RC0603FR-07499RL)
R235  ValueDisplayed: 0  [0603]  (hidden comment: RC0603JR-070RL)
R236  ValueDisplayed: 0  [0603]  (hidden comment: RC0603JR-070RL)
R237  ValueDisplayed: 10  [0603]  (hidden comment: CRCW060310R0JNEA)
R238  ValueDisplayed: 43  [0603]  (hidden comment: CRCW060343R0JNEA)
R245  ValueDisplayed: 0  [0603]  (hidden comment: RC0603JR-070RL)
R246  ValueDisplayed: 0  [0603]  (hidden comment: RC0603JR-070RL)
R247  ValueDisplayed: 10  [0603]  (hidden comment: CRCW060310R0JNEA)
R248  ValueDisplayed: 43  [0603]  (hidden comment: CRCW060343R0JNEA)
R249  ValueDisplayed: 499  [0603]  (hidden comment: RC0603FR-07499RL)
R250  ValueDisplayed: 1.00k  [0603]  (hidden comment: CRCW06031K00FKEA)
R251  ValueDisplayed: 499  [0603]  (hidden comment: RC0603FR-07499RL)
R252  ValueDisplayed: 0  [0603]  (hidden comment: RC0603JR-070RL)
R253  ValueDisplayed: 0  [0603]  (hidden comment: RC0603JR-070RL)
R254  ValueDisplayed: 10  [0603]  (hidden comment: CRCW060310R0JNEA)
R255  ValueDisplayed: 43  [0603]  (hidden comment: CRCW060343R0JNEA)
T3  LKBMT10B  [FP-LKBMT10B_SMT_XFRMR_27MM9_12MM5-MFG]
T4  LKBMT10B  [FP-LKBMT10B_SMT_XFRMR_27MM9_12MM5-MFG]

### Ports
COMHN (bidir), COMHP (bidir), COMLN (bidir), COMLP (bidir)

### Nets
GND: C98.2 C99.2 C100.1 C101.1 C104.2 C105.2 C106.1 C107.1 D20.3(GND) D22.3(GND) J34.3 J39.3
COMH_CT: C106.2 R249.1 R251.2
COMHN: C104.1 J39.1 R248.2 R249.2 R250.2 ; port COMHN
COMHN_ISO: J37.4 J38.1 R245.1
COMHN_OPT: R246.2 R247.1
COMHN_R: D22.2(2_IO) R247.2 R248.1
COMHN_XFMR: R246.1 T4.6
COMHN_XFMR_O: D24.1 R245.2 T4.1
COMHP: C107.2 J39.2 R250.1 R251.1 R255.2 ; port COMHP
COMHP_ISO: J37.1 J38.2 R252.1
COMHP_OPT: R253.2 R254.1
COMHP_R: D22.1(1_IO) R254.2 R255.1
COMHP_XFMR: R253.1 T4.4
COMHP_XFMR_O: D24.2 R252.2 T4.3
COML_CT: C100.2 R232.1 R234.2
COML_XFMR: C99.1 T3.5
COMLN: C101.2 J34.2 R233.1 R234.1 R238.2 ; port COMLN
COMLN_ISO: J35.2 J36.1 R235.1
COMLN_OPT: R236.2 R237.1
COMLN_R: D20.1(1_IO) R237.2 R238.1
COMLN_XFMR: R236.1 T3.4
COMLN_XFMR_O: D23.1 R235.2 T3.3
COMLP: C98.1 J34.1 R231.2 R232.2 R233.2 ; port COMLP
COMLP_ISO: J35.1 J36.4 R228.1
COMLP_OPT: R229.2 R230.1
COMLP_R: D20.2(2_IO) R230.2 R231.1
COMLP_XFMR: R229.1 T3.6
COMLP_XFMR_O: D23.2 R228.2 T3.1
NetC105_1: C105.1 T4.5

Not connected (* = marked no-connect by the designer): J36 2* 3*; J37 2* 3*; T3 2; T4 2

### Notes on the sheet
- Labels drawn without touching a wire or pin: COMH_XFMR

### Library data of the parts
C98 C101 C104 C107 = CMP-0860329-1: CAP, CERM, 220 pF, 50 V,+/- 5%, X7R, 0603; Manufacturer: Samsung Electro-Mechanics; TaMin_C: -55°C; Polarized: N; SizeAreaWB_mm2: 4.68; U/M: EA; Value: 220pF; TaMax_C: 125°C; SizeZ_mm: 1; SizeX_mm: 1.6; SizeY_mm: 0.8; Value2: 50V; SizeArea_mm2: 1.28; CompType: Capacitor; AEC Category: Q200
C99 C105 = CMP-0750041-1: CAP, CERM, 100 pF, 50 V,+/- 5%, C0G/NP0, AEC-Q200 Grade 1, 0603; Manufacturer: MuRata; TaMin_C: -55°C; Polarized: N; SizeAreaWB_mm2: 4.68; U/M: EA; Value: 100pF; TaMax_C: 125°C; SizeZ_mm: 1; SizeX_mm: 1.6; SizeY_mm: 0.8; Value2: 50V; SizeArea_mm2: 1.28; AEC Qualified: Y; AEC Category: Q200
C100 C106 = CMP-0007109-5: CAP, CERM, 0.01 uF, 50 V, +/- 10%, X7R, 0603; Manufacturer: Samsung Electro-Mechanics; TaMin_C: -55°C; Polarized: N; SizeAreaWB_mm2: 4.68; Value1: Unknown; U/M: EA; Value: 0.01uF; TaMax_C: 125°C; SizeZ_mm: 1; SizeX_mm: 1.6; SizeY_mm: 0.8; Value2: 50V; SizeArea_mm2: 1.28; CompType: Capacitor; AEC Category: Q200
D20 D22 = CMP-0120582-1: 12-V Bi-directional ESD protection diode in SOT-23; Manufacturer: Texas Instruments; SizeZ_mm: 1.12mm; AEC Qualified: No; Breakdown Voltage: 13.3V; Clamping Voltage: 24V; Direction: Bidirectional; Ipp: 20A; Number Of Channels: 2; Ppk: 500W; Standoff Height: 0.01mm; TaMax_C: +125°C; TaMin_C: -40°C; VRWM: 12V
D23 D24 = CMP-0065114-2: Diode, TVS, Bi, 8 V, 18.5 Vc, SOD-323; Manufacturer: Bourns; SizeAreaWB_mm2: 8.695; Ppk: 400W; SizeArea_mm2: 3.645; AEC Qualified: N; SizeY_mm: 1.35; Ipp: 17A; Vbr_Min: 8.5V; Vc: 18.5V; SizeZ_mm: 1.0; SizeX_mm: 2.7; AEC Category: Q101
J34 J39 = CMP-0075407-2: Header, 100mil, 3x1, Gold, TH; Manufacturer: Samtec; Pitch_mm: 2.54; Cert_VDE: N; Gender: Male; Cert_CSA: Y; Voltage_V: 550V; Green_REACh: Passed; Current_A: 6.3A; Green_Lifecycle: Active; Row_Count: 1
J35 J38 = CMP-0075626-1: Header, 100mil, 2x1, Gold, TH; Manufacturer: Samtec; Pitch_mm: 2.54; Gender: Male; Cert_CSA: Y; CT: False; Row_Count: 1
J36 J37 = CMP-0055239-1: Header(shrouded), 2.54mm, 4x1, R/A, Gold, TH; Manufacturer: Molex; CNHeader: FALSE; Current_A: 3A; Green_Lifecycle: Active; Shrouded: Y; Gender: Male; Green_REACh: Passed; Voltage_V: 250V; Row_Count: 1; Pitch_mm: 2.54
R228 R229 R235 R236 R245 R246 R252 R253 = CMP-0025885-5: RES, 0, 5%, 0.1 W, 0603; Manufacturer: Yageo; Power_W: 100mW; TempCo: 200 ppm/C; Value_Code: 0000; Value: 0; EIA_Code: E24; SizeX_mm: 1.6; SizeZ_mm: 1; Value2: 0.1W; SizeArea_mm2: 1.28; AEC Qualified: N; VDC_V: 75V; AEC Category: Q200; SizeY_mm: 0.8; SizeAreaWB_mm2: 4.68
R230 R237 R247 R254 = CMP-0025703-4: RES, 10, 5%, 0.1 W, AEC-Q200 Grade 0, 0603; Manufacturer: Vishay-Dale; Power_W: 100mW; TempCo: 200 ppm/C; Value_Code: 10R0; Value: 10; EIA_Code: E24; SizeX_mm: 1.6; SizeY_mm: 0.8; SizeZ_mm: 1; Value2: 0.1W; SizeArea_mm2: 1.28; AEC Qualified: Y; VDC_V: 75V; AEC Category: Q200; AEC Grade: 0
R231 R238 R248 R255 = CMP-0025811-4: RES, 43, 5%, 0.1 W, AEC-Q200 Grade 0, 0603; Manufacturer: Vishay-Dale; Power_W: 100mW; TempCo: 200 ppm/C; Value_Code: 43R0; Value: 43; EIA_Code: E24; SizeX_mm: 1.6; SizeY_mm: 0.8; SizeZ_mm: 1; Value2: 0.1W; SizeArea_mm2: 1.28; AEC Qualified: Y; VDC_V: 75V; AEC Category: Q200; AEC Grade: 0
R232 R234 R249 R251 = CMP-0023141-5: RES, 499, 1%, 0.1 W, 0603; Manufacturer: Yageo; Power_W: 100mW; TempCo: 100 ppm/C; Value_Code: 499R; Value: 499; EIA_Code: E96; SizeX_mm: 1.6; SizeY_mm: 0.8; SizeZ_mm: 1; Value2: 0.1W; SizeArea_mm2: 1.28; AEC Qualified: N; VDC_V: 75V; AEC Category: Q200; SizeAreaWB_mm2: 4.68
R233 R250 = CMP-0022109-5: RES, 1.00 k, 1%, 0.1 W, AEC-Q200 Grade 0, 0603; Manufacturer: Vishay-Dale; Power_W: 100mW; TempCo: 100 ppm/C; Value_Code: 1k00; Value: 1.00k; EIA_Code: E96; Res_ohm: 1k; SizeX_mm: 1.6; SizeY_mm: 0.8; SizeZ_mm: 1; Value2: 0.1W; SizeArea_mm2: 1.28; AEC Qualified: Y; VDC_V: 75V; AEC Category: Q200; AEC Grade: 0
T3 T4 = CMP-0122349-1: SMD BMS Transformer; Manufacturer: LineKey Technology; DCR_ohm: 0.8; Ind_H: 300µH; Ns1toNp: 1:1; Rsec1_ohm: 1; SizeZ_mm: 9.5mm; AEC Qualified: Yes; AEC Grade: Grade 1; Insertion Loss: -0.5dB; Return Loss: -20dB; Voltage_Isolation_Vrms: 5000VDC

## Sheet CurrentSense_2CH.SchDoc
size 431 x 279 mm; SheetNumber: 4; SheetTotal: 10
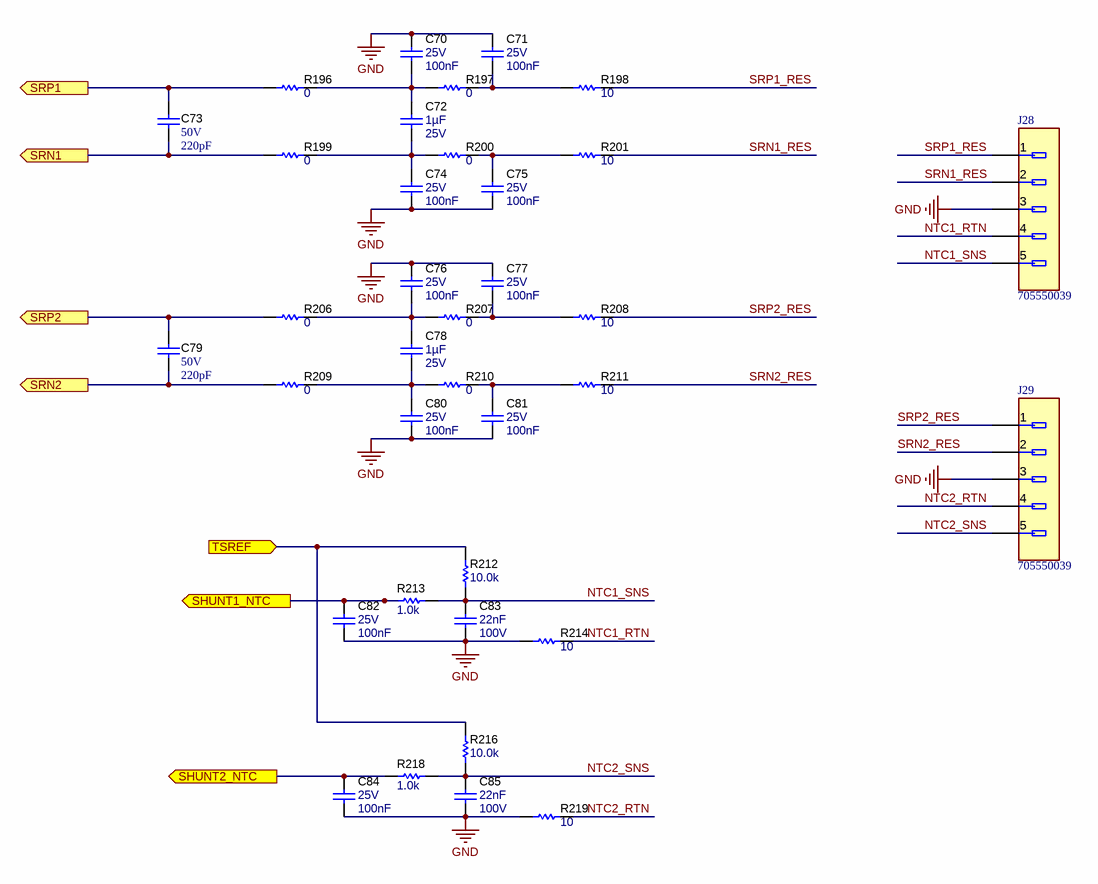
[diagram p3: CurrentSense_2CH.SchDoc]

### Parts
C70  VDC_V: 25V  Cap_F: 100nF  [0603]  (hidden comment: GCM188R71E104KA57D)
C71  VDC_V: 25V  Cap_F: 100nF  [0603]  (hidden comment: GCM188R71E104KA57D)
C72  Cap_F: 1µF  VDC_V: 25V  [0603]  (hidden comment: GCM188R71E105KA64D)
C73  VDC_V: 50V  ValueDisplayed: 220pF  [FP-GCM1555C1H221JA16D_0402-MFG]  (hidden comment: GCM1555C1H221JA16D)
C74  VDC_V: 25V  Cap_F: 100nF  [0603]  (hidden comment: GCM188R71E104KA57D)
C75  VDC_V: 25V  Cap_F: 100nF  [0603]  (hidden comment: GCM188R71E104KA57D)
C76  VDC_V: 25V  Cap_F: 100nF  [0603]  (hidden comment: GCM188R71E104KA57D)
C77  VDC_V: 25V  Cap_F: 100nF  [0603]  (hidden comment: GCM188R71E104KA57D)
C78  Cap_F: 1µF  VDC_V: 25V  [0603]  (hidden comment: GCM188R71E105KA64D)
C79  VDC_V: 50V  ValueDisplayed: 220pF  [FP-GCM1555C1H221JA16D_0402-MFG]  (hidden comment: GCM1555C1H221JA16D)
C80  VDC_V: 25V  Cap_F: 100nF  [0603]  (hidden comment: GCM188R71E104KA57D)
C81  VDC_V: 25V  Cap_F: 100nF  [0603]  (hidden comment: GCM188R71E104KA57D)
C82  VDC_V: 25V  Cap_F: 100nF  [0603]  (hidden comment: GCM188R71E104KA57D)
C83  Cap_F: 22nF  VDC_V: 100V  [0603]  (hidden comment: CGA3E2X7R2A223K080AA)
C84  VDC_V: 25V  Cap_F: 100nF  [0603]  (hidden comment: GCM188R71E104KA57D)
C85  Cap_F: 22nF  VDC_V: 100V  [0603]  (hidden comment: CGA3E2X7R2A223K080AA)
J28  705550039  [705550039]
J29  705550039  [705550039]
R196  ValueDisplayed: 0  [0603]  (hidden comment: CRCW06030000Z0EA)
R197  ValueDisplayed: 0  [0603]  (hidden comment: CRCW06030000Z0EA)
R198  ValueDisplayed: 10  [0603]  (hidden comment: CRCW060310R0JNEA)
R199  ValueDisplayed: 0  [0603]  (hidden comment: CRCW06030000Z0EA)
R200  ValueDisplayed: 0  [0603]  (hidden comment: CRCW06030000Z0EA)
R201  ValueDisplayed: 10  [0603]  (hidden comment: CRCW060310R0JNEA)
R206  ValueDisplayed: 0  [0603]  (hidden comment: CRCW06030000Z0EA)
R207  ValueDisplayed: 0  [0603]  (hidden comment: CRCW06030000Z0EA)
R208  ValueDisplayed: 10  [0603]  (hidden comment: CRCW060310R0JNEA)
R209  ValueDisplayed: 0  [0603]  (hidden comment: CRCW06030000Z0EA)
R210  ValueDisplayed: 0  [0603]  (hidden comment: CRCW06030000Z0EA)
R211  ValueDisplayed: 10  [0603]  (hidden comment: CRCW060310R0JNEA)
R212  ValueDisplayed: 10.0k  [0603]  (hidden comment: CRCW060310K0FKEA)
R213  ValueDisplayed: 1.0k  [0603]  (hidden comment: CRCW06031K00JNEA)
R214  ValueDisplayed: 10  [0603]  (hidden comment: CRCW060310R0JNEA)
R216  ValueDisplayed: 10.0k  [0603]  (hidden comment: CRCW060310K0FKEA)
R218  ValueDisplayed: 1.0k  [0603]  (hidden comment: CRCW06031K00JNEA)
R219  ValueDisplayed: 10  [0603]  (hidden comment: CRCW060310R0JNEA)

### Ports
SHUNT1_NTC (out), SHUNT2_NTC (out), SRN1 (out), SRN2 (out), SRP1 (out), SRP2 (out), TSREF (in)

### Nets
GND: C70.1 C71.1 C74.2 C75.2 C76.1 C77.1 C80.2 C81.2 C82.2 C83.2 C84.2 C85.2 J28.3 J29.3 R214.1 R219.1
TSREF: R212.2 R216.2 ; port TSREF
NTC1: C82.1 R213.1 ; port SHUNT1_NTC
NTC1_RTN: J28.4 R214.2
NTC1_SNS: C83.1 J28.5 R212.1 R213.2
NTC2: C84.1 R218.1 ; port SHUNT2_NTC
NTC2_RTN: J29.4 R219.2
NTC2_SNS: C85.1 J29.5 R216.1 R218.2
SRN1: C73.2 R199.2 ; port SRN1
SRN1_RES: J28.2 R201.2
SRN2: C79.2 R209.2 ; port SRN2
SRN2_RES: J29.2 R211.2
SRP1: C73.1 R196.2 ; port SRP1
SRP1_RES: J28.1 R198.2
SRP2: C79.1 R206.2 ; port SRP2
SRP2_RES: J29.1 R208.2
NetC70_2: C70.2 C72.1 R196.1 R197.2
NetC71_2: C71.2 R197.1 R198.1
NetC72_2: C72.2 C74.1 R199.1 R200.2
NetC75_1: C75.1 R200.1 R201.1
NetC76_2: C76.2 C78.1 R206.1 R207.2
NetC77_2: C77.2 R207.1 R208.1
NetC78_2: C78.2 C80.1 R209.1 R210.2
NetC81_1: C81.1 R210.1 R211.1

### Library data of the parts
C70 C71 C74-C77 C80-C82 C84 = CMP-0084679-1: CAP, CERM, 0.1 µF, 25 V,+/- 10%, X7R, AEC-Q200 Grade 1, 0603; Manufacturer: MuRata; TaMin_C: -55°C; SizeY_mm: 0.8; Polarized: N; SizeArea_mm2: 1.28; SizeZ_mm: 1; SizeX_mm: 1.6; AEC Qualified: Y; AEC Category: Q200; Value: 0.1uF; ValueDisplayed: 0.1µF; TaMax_C: 125°C; U/M: EA; SizeAreaWB_mm2: 4.68
C72 C78 = CMP-0007139-4: CAP, CERM, 1 uF, 25 V, +/- 10%, X7R, AEC-Q200 Grade 1, 0603; Manufacturer: MuRata; TaMin_C: -55°C; Polarized: N; SizeAreaWB_mm2: 4.68; Value1: Unknown; U/M: EA; Value: 1uF; TaMax_C: 125°C; SizeZ_mm: 1; SizeX_mm: 1.6; SizeY_mm: 0.8; SizeArea_mm2: 1.28; AEC Qualified: Y; AEC Category: Q200
C73 C79 = CMP-0088015-1: 220pF Multilayer Ceramic Capacitor (MLCC) 50 V dc 5% C0G dielectric GCM max op. temp. +125C; Manufacturer: Murata Electronics North America; Cap_F: 0.22nF; TempCo: 30ppm/°C; AEC Qualified: Yes; SizeZ_mm: 0.55mm; AEC Grade: Grade 1
C83 C85 = CMP-0007086-4: CAP, CERM, 0.022 uF, 100 V, +/- 10%, X7R, AEC-Q200 Grade 1, 0603; Manufacturer: TDK; TaMin_C: -55°C; ESR_ohm: 0.083542; Polarized: N; SizeAreaWB_mm2: 4.68; Value1: 0.083542 ohm; U/M: EA; TaMax_C: 125°C; SizeZ_mm: 1; SizeX_mm: 1.6; SizeY_mm: 0.8; SizeArea_mm2: 1.28; AEC Qualified: Y; IRMS_A: 6.09312dA; AEC Category: Q200
J28 J29 = 5P_705550039: Connector Header Through Hole, Right Angle 5 position 0.100" (2.54mm); Manufacturer: Molex
R196 R197 R199 R200 R206 R207 R209 R210 = CMP-0025697-4: as R405 on sheet HMU
R198 R201 R208 R211 R214 R219 = CMP-0025703-4: as R230 on sheet DaisyChain_2CH
R212 R216 = CMP-0021998-4: RES, 10.0 k, 1%, 0.1 W, AEC-Q200 Grade 0, 0603; Manufacturer: Vishay-Dale; Power_W: 100mW; TempCo: 100 ppm/C; Value_Code: 10k0; Value: 10.0k; EIA_Code: E96; Res_ohm: 10k; SizeX_mm: 1.6; SizeY_mm: 0.8; SizeZ_mm: 1; Value2: 0.1W; SizeArea_mm2: 1.28; AEC Qualified: Y; VDC_V: 75V; AEC Category: Q200; AEC Grade: 0
R213 R218 = CMP-0025729-4: RES, 1.0 k, 5%, 0.1 W, AEC-Q200 Grade 0, 0603; Manufacturer: Vishay-Dale; Power_W: 100mW; TempCo: 200 ppm/C; Value_Code: 1k00; Value: 1.0k; EIA_Code: E24; Res_ohm: 1k; SizeX_mm: 1.6; SizeY_mm: 0.8; SizeZ_mm: 1; Value2: 0.1W; SizeArea_mm2: 1.28; AEC Qualified: Y; VDC_V: 75V; AEC Category: Q200; AEC Grade: 0

## Sheet HVSense_1CH.SchDoc
size A4; SheetNumber: 2; SheetTotal: 10
Used 3 times, as channels HV1, HV3, HV4. Parts and nets are listed once, with the designators drawn on the sheet.
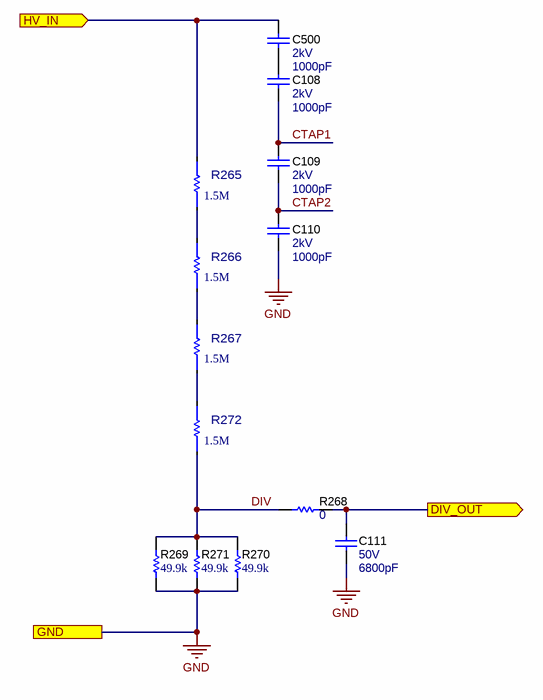
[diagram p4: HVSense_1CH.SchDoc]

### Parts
C108  VDC_V: 2kV  ValueDisplayed: 1000pF  [1206_180]  (hidden comment: C1206C102KGRACAUTO)
C109  VDC_V: 2kV  ValueDisplayed: 1000pF  [1206_180]  (hidden comment: C1206C102KGRACAUTO)
C110  VDC_V: 2kV  ValueDisplayed: 1000pF  [1206_180]  (hidden comment: C1206C102KGRACAUTO)
C111  VDC_V: 50V  ValueDisplayed: 6800pF  [0603]  (hidden comment: GRM1885C1H682JA01D)
C500  VDC_V: 2kV  ValueDisplayed: 1000pF  [1206_180]  (hidden comment: C1206C102KGRACAUTO)
R265  value 1.5M  [FP-CHV1206-FX-1504ELF_1206-MFG]  (hidden comment: CHV1206-FX-1504ELF)
R266  value 1.5M  [FP-CHV1206-FX-1504ELF_1206-MFG]  (hidden comment: CHV1206-FX-1504ELF)
R267  value 1.5M  [FP-CHV1206-FX-1504ELF_1206-MFG]  (hidden comment: CHV1206-FX-1504ELF)
R268  ValueDisplayed: 0  [0603]  (hidden comment: CRCW06030000Z0EA)
R269  ValueDisplayed: 49.9k  [0603]  (hidden comment: RC0603FR-0749K9L)
R270  ValueDisplayed: 49.9k  [0603]  (hidden comment: RC0603FR-0749K9L)
R271  ValueDisplayed: 49.9k  [0603]  (hidden comment: RC0603FR-0749K9L)
R272  value 1.5M  [FP-CHV1206-FX-1504ELF_1206-MFG]  (hidden comment: CHV1206-FX-1504ELF)

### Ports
DIV_OUT (out), GND, HV_IN (in)

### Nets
GND: C110.2 C111.2 R269.1 R270.1 R271.1 ; port GND
CTAP1: C108.2 C109.1
CTAP2: C109.2 C110.1
DIV: R268.2 R269.2 R270.2 R271.2 R272.1
DIV_OUT: C111.1 R268.1 ; port DIV_OUT
HV_IN: C500.1 R265.2 ; port HV_IN
NetC108_1: C108.1 C500.2
NetR265_1: R265.1 R266.2
NetR266_1: R266.1 R267.2
NetR267_1: R267.1 R272.2

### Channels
HV1: designators end in _HV1; ports DIV_OUT=DIV_OUT GND=GND HV_IN=BATP
HV3: designators end in _HV3; ports DIV_OUT=DIV_OUT GND=GND HV_IN=RACKP
HV4: designators end in _HV4; ports DIV_OUT=DIV_OUT GND=GND HV_IN=RACKN

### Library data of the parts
C108-C110 C500 = CMP-0008579-2: CAP, CERM, 1000 pF, 2000 V, +/- 10%, X7R, AEC-Q200 Grade 1, 1206; Manufacturer: Kemet; TaMin_C: -55°C; Polarized: N; SizeAreaWB_mm2: 10.92; Value1: Unknown; U/M: EA; Value: 1000pF; TaMax_C: 125°C; SizeZ_mm: 1.8; SizeX_mm: 3.2; SizeY_mm: 1.6; Cap_Case: 1206; Value2: 2000V; SizeArea_mm2: 5.12; AEC Qualified: Y; Cap_F: 1nF; AEC Grade: 1; AEC Category: Q200
C111 = CMP-0078296-1: CAP, CERM, 6800 pF, 50 V,+/- 5%, C0G/NP0, 0603; Manufacturer: MuRata; TaMin_C: -55°C; Polarized: N; SizeAreaWB_mm2: 4.68; U/M: EA; Value: 6800pF; TaMax_C: 125°C; SizeZ_mm: 1; SizeX_mm: 1.6; SizeY_mm: 0.8; SizeArea_mm2: 1.28; Cap_F: 6.8nF; AEC Category: Q200
R265-R267 R272 = CMP-0120473-1: as R300 on sheet HMU
R268 = CMP-0025697-4: as R405 on sheet HMU
R269-R271 = CMP-0023142-5: RES, 49.9 k, 1%, 0.1 W, 0603; Manufacturer: Yageo; Power_W: 100mW; TempCo: 100 ppm/C; Value_Code: 49k9; Value: 49.9k; EIA_Code: E96; SizeX_mm: 1.6; SizeY_mm: 0.8; SizeZ_mm: 1; Value2: 0.1W; SizeArea_mm2: 1.28; AEC Qualified: N; VDC_V: 75V; AEC Category: Q200; SizeAreaWB_mm2: 4.68

## Sheet GPIO_Matrix.SchDoc
size 431 x 279 mm; Date: Not shown in title block; ApprovedBy: Not shown in title block; CheckedBy: Not shown in title block; Author: Not shown in title block; CompanyName: Not shown in title block; Engineer: Not shown in title block; Organization: Not shown in title block; Address1: Not shown in title block; Address2: Not shown in title block; Address3: Not shown in title block; Address4: Not shown in title block; DocumentNumber: TIDA-010272; Revision: Use project parameter SCH_Rev; SheetNumber: 8; SheetTotal: 10; PageSetup: Record=PageOptions¦CenterHorizontal=True¦CenterVertical=True¦PrintScale=1.00¦XCorrection=1.00¦YCorrection=1.00¦PrintKind=0¦BorderSize=5000000¦LeftOffset=0¦BottomOffset=0¦Orientation=2¦PaperLength=1000¦PaperWidth=1000¦Scale=100¦PaperSource=15¦PrintQuality=600¦MediaType=1¦DitherType=10¦PaperKind=Letter¦PrintScaleMode=1
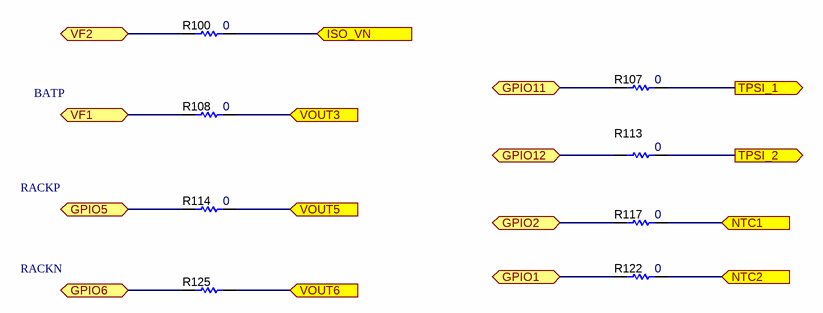
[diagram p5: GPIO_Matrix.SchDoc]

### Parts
R100  ValueDisplayed: 0  [0603]  (hidden comment: CRCW06030000Z0EA)
R107  ValueDisplayed: 0  [0603]  (hidden comment: CRCW06030000Z0EA)
R108  ValueDisplayed: 0  [0603]  (hidden comment: CRCW06030000Z0EA)
R113  ValueDisplayed: 0  [0603]  (hidden comment: CRCW06030000Z0EA)
R114  ValueDisplayed: 0  [0603]  (hidden comment: CRCW06030000Z0EA)
R117  ValueDisplayed: 0  [0603]  (hidden comment: CRCW06030000Z0EA)
R122  ValueDisplayed: 0  [0603]  (hidden comment: CRCW06030000Z0EA)
R125  CRCW06030000Z0EA  [0603]  (value not drawn)

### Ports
GPIO1 (bidir), GPIO2 (bidir), GPIO5 (bidir), GPIO6 (bidir), GPIO11 (bidir), GPIO12 (bidir), ISO_VN (in), NTC1 (in), NTC2 (in), TPSI_1 (out), TPSI_2 (out), VF1 (bidir), VF2 (bidir), VOUT3 (in), VOUT5 (in), VOUT6 (in)

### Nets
DIV_OUT: R108.2 ; port VOUT3
DIV_OUT: R114.2 ; port VOUT5  [a separate net that carries the same name]
DIV_OUT: R125.2 ; port VOUT6  [a separate net that carries the same name]
GPIO1: R122.1 ; port GPIO1
GPIO2: R117.1 ; port GPIO2
GPIO5: R114.1 ; port GPIO5
GPIO6: R125.1 ; port GPIO6
GPIO11: R107.1 ; port GPIO11
GPIO12: R113.1 ; port GPIO12
HS_SW_DRV: R107.2 ; port TPSI_1
ISO_VN: R100.2 ; port ISO_VN
LS_SW_DRV: R113.2 ; port TPSI_2
NTC1: R117.2 ; port NTC1
NTC2: R122.2 ; port NTC2
VF1: R108.1 ; port VF1
VF2: R100.1 ; port VF2

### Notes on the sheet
- BATP
- RACKP
- RACKN

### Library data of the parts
R100 R107 R108 R113 R114 R117 R122 R125 = CMP-0025697-4: as R405 on sheet HMU

## Sheet ISO_SPI.SchDoc
size 431 x 279 mm; SheetNumber: 3; SheetTotal: 10
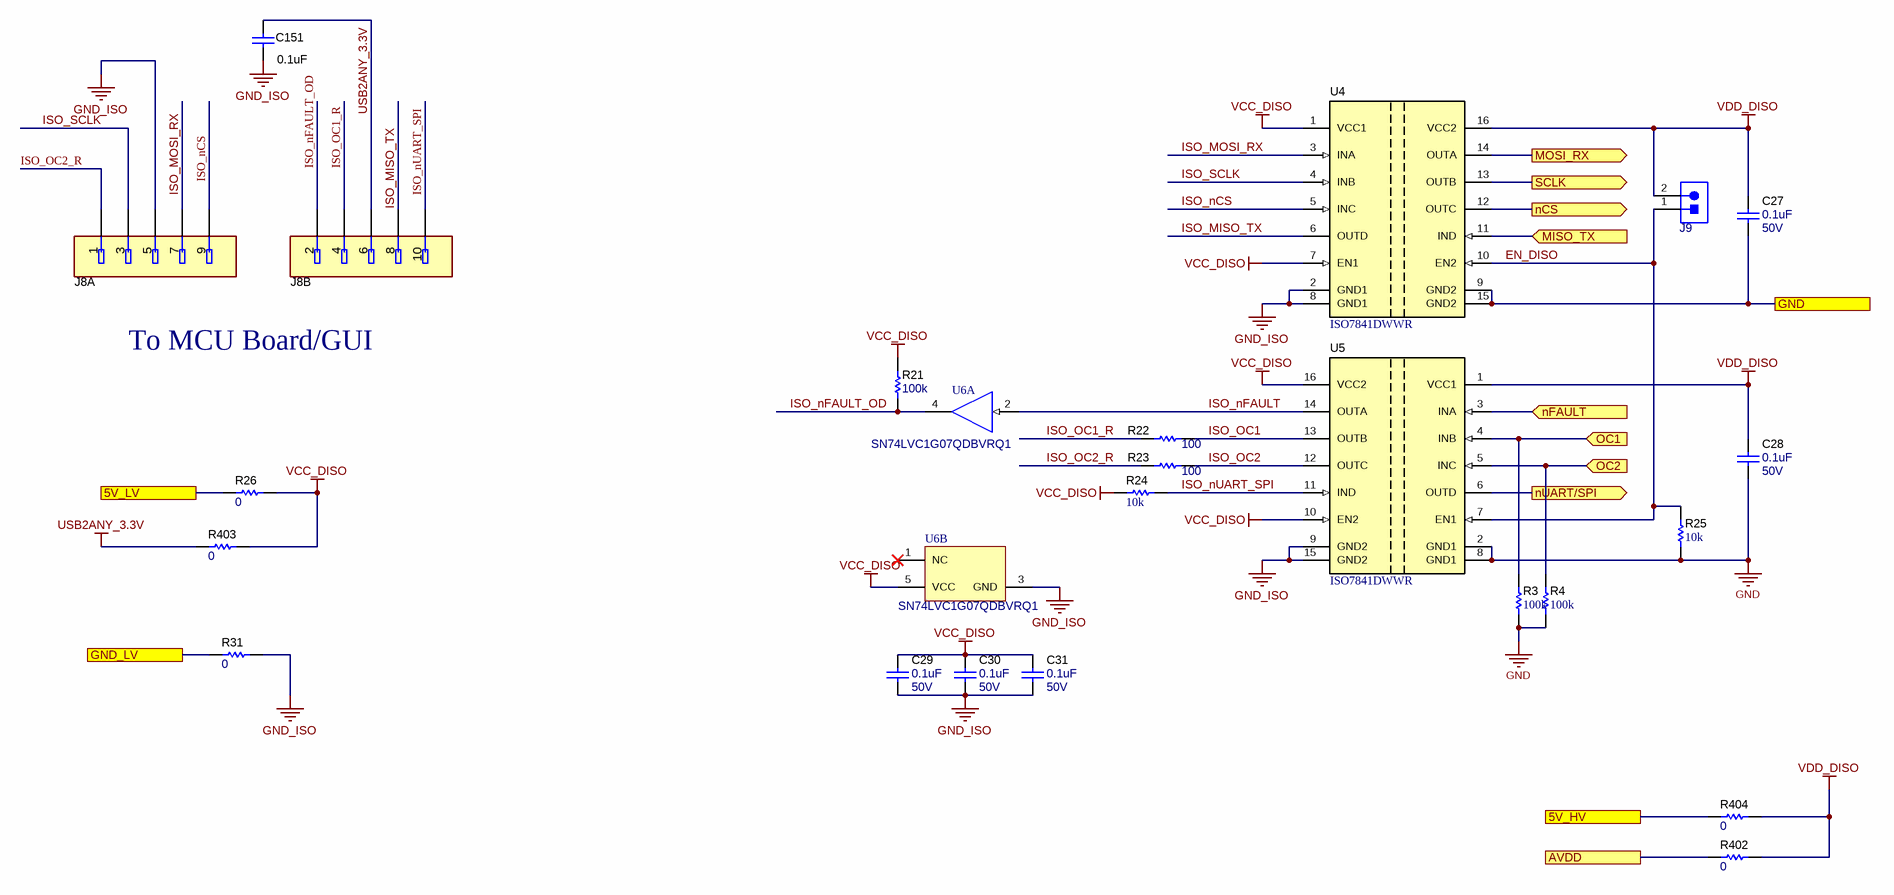
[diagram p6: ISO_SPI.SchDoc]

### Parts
C27  VDC_V: 50V  ValueDisplayed: 0.1uF  [0402]  (hidden comment: GCM155R71H104KE02D)
C28  VDC_V: 50V  ValueDisplayed: 0.1uF  [0402]  (hidden comment: GCM155R71H104KE02D)
C29  VDC_V: 50V  ValueDisplayed: 0.1uF  [0402]  (hidden comment: GCM155R71H104KE02D)
C30  VDC_V: 50V  ValueDisplayed: 0.1uF  [0402]  (hidden comment: GCM155R71H104KE02D)
C31  VDC_V: 50V  ValueDisplayed: 0.1uF  [0402]  (hidden comment: GCM155R71H104KE02D)
C151  ValueDisplayed: 0.1uF  [0402]  (hidden comment: GCM155R71A104KA55D)
J8  TSW-105-08-L-D-RA  [FP-TSW-105-08-L-D-RA_HDR10-MFG]  (value not drawn)  (parts A,B of 2)
J9  PEC02SAAN  [CONN_PEC02SAAN]  (value not drawn)
R3  ValueDisplayed: 100k  [0603_HR]  (hidden comment: RR0816P-104-D)
R4  ValueDisplayed: 100k  [0603_HR]  (hidden comment: RR0816P-104-D)
R21  ValueDisplayed: 100k  [0402]  (hidden comment: CRCW0402100KDHEDP)
R22  ValueDisplayed: 100  [0402]  (hidden comment: CRCW0402100RJNED)
R23  ValueDisplayed: 100  [0402]  (hidden comment: CRCW0402100RJNED)
R24  ValueDisplayed: 10k  [0402]  (hidden comment: CRCW040210K0JNED)
R25  ValueDisplayed: 10k  [0402]  (hidden comment: CRCW040210K0JNED)
R26  ValueDisplayed: 0  [0603]  (hidden comment: CRCW06030000Z0EA)
R31  ValueDisplayed: 0  [0603]  (hidden comment: CRCW06030000Z0EA)
R402  ValueDisplayed: 0  [0603]  (hidden comment: CRCW06030000Z0EA)
R403  ValueDisplayed: 0  [0603]  (hidden comment: CRCW06030000Z0EA)
R404  ValueDisplayed: 0  [0603]  (hidden comment: CRCW06030000Z0EA)
U4  ISO7841DWWR  [DWW0016A_N]
U5  ISO7841DWWR  [DWW0016A_N]
U6  SN74LVC1G07QDBVRQ1  [DBV0005A_N]  (parts A,B of 2)

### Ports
5V_HV, 5V_LV, AVDD, GND, GND_LV, MISO_TX (in), MOSI_RX (out), nCS (out), nFAULT (in), nUART/SPI (out), OC1 (in), OC2 (in), SCLK (out)

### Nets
AVDD: R402.1 ; port AVDD
GND: C27.2 C28.2 R3.1 R4.1 R25.1 U4.9(GND2) U4.15(GND2) U5.2(GND1) U5.8(GND1) ; port GND
GND_ISO: C29.2 C30.2 C31.2 C151.1 J8.5 R31.2 U4.2(GND1) U4.8(GND1) U5.9(GND2) U5.15(GND2) U6.3(GND)
GND_LV: R31.1 ; port GND_LV
USB2ANY_3.3V: C151.2 J8.6 R403.1
VCC_DISO: C29.1 C30.1 C31.1 R21.2 R24.2 R26.2 R403.2 U4.1(VCC1) U4.7(EN1) U5.10(EN2) U5.16(VCC2) U6.5(VCC)
VDD_DISO: C27.1 C28.1 J9.2 R402.2 R404.2 U4.16(VCC2) U5.1(VCC1)
5V_HV: R404.1 ; port 5V_HV
5V_LV: R26.1 ; port 5V_LV
EN_DISO: J9.1 R25.2 U4.10(EN2) U5.7(EN1)
ISO_MISO_TX: J8.8 U4.6(OUTD)
ISO_MOSI_RX: J8.7 U4.3(INA)
ISO_nCS: J8.9 U4.5(INC)
ISO_nFAULT: U5.14(OUTA) U6.2(A)
ISO_nFAULT_OD: J8.2 R21.1 U6.4(Y)
ISO_nUART_SPI: J8.10 R24.1 U5.11(IND)
ISO_OC1: R22.2 U5.13(OUTB)
ISO_OC1_R: J8.4 R22.1
ISO_OC2: R23.2 U5.12(OUTC)
ISO_OC2_R: J8.1 R23.1
ISO_SCLK: J8.3 U4.4(INB)
MISO_TX: U4.11(IND) ; port MISO_TX
MOSI_RX: U4.14(OUTA) ; port MOSI_RX
nCS: U4.12(OUTC) ; port nCS
nFAULT: U5.3(INA) ; port nFAULT
nUART/SPI: U5.6(OUTD) ; port nUART/SPI
OC1: R3.2 U5.4(INB) ; port OC1
OC2: R4.2 U5.5(INC) ; port OC2
SCLK: U4.13(OUTB) ; port SCLK

Not connected (* = marked no-connect by the designer): U6 1(NC)*

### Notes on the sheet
- To MCU Board/GUI

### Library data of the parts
C27-C31 = CMP-0006356-2: as C89 on sheet UIR_Board_BQ79731
C151 = CMP-0006350-2: CAP, CERM, 0.1 uF, 10 V, +/- 10%, X7R, AEC-Q200 Grade 1, 0402; Manufacturer: MuRata; TaMin_C: -55°C; Polarized: N; SizeAreaWB_mm2: 3; Value1: Unknown; U/M: EA; Value: 0.1uF; TaMax_C: 125°C; SizeZ_mm: 0.6; SizeX_mm: 1; SizeY_mm: 0.5; Value2: 10V; CompType: Capacitor; AEC Qualified: Y; Cap_F: 100nF; AEC Category: Q200
J8 = CMP-0086439-1: CONN HEADER 10POS .100 DL R/A AU; Manufacturer: Wurth Elektronik; PartNumber: 61301021021; Row_Count: 2; Voltage_V: 550V; ContactFinish: Gold,Nickel; Current_A: 6.3A; Symbol Name: SYM-TSW-105-08-L-D-RA
J9 = CMP-0002337-1: Header, 100mil, 2x1, Tin, TH; Manufacturer: Sullins Connector Solutions; CNHeader: TRUE; Current_A: 3A; Green_Lifecycle: Not Set; Shrouded: N; Gender: Male; Green_REACh: Incomplete; Voltage_V: 1.8kV; Row_Count: 1; Pitch_mm: 2.54; CT: FALSE; Cert_UL: Y
R3 R4 = CMP-0065353-2: RES, 100 k, .5%, .0625 W, 0603; Manufacturer: Susumu Co Ltd; Power_W: 62.5mW; TempCo: 25 ppm/C; U/M: EA; Value: 100k; EIA_Code: E192; Tolerance_%: 0.5%; SizeX_mm: 1.55; SizeY_mm: 0.85; SizeZ_mm: 0.5; Value2: .0625W; SizeArea_mm2: 1.3175; AEC Qualified: N; VDC_V: 75V; AEC Category: Q200
R21 = CMP-0026768-2: RES, 100 k, 0.5%, 0.063 W, AEC-Q200 Grade 0, 0402; Manufacturer: Vishay-Dale; Power_W: 63mW; TempCo: 50 ppm/C; Value: 100k; EIA_Code: E192; SizeX_mm: 1; SizeY_mm: 0.5; SizeZ_mm: 0.6; Value2: 0.063W; AEC Qualified: Y; VDC_V: 50V; AEC Category: Q200; AEC Grade: 0
R22 R23 = CMP-0026824-3: RES, 100, 5%, 0.063 W, AEC-Q200 Grade 0, 0402; Manufacturer: Vishay-Dale; Power_W: 63mW; TempCo: 200 ppm/C; Value_Code: 100R; Value: 100; EIA_Code: E24; SizeX_mm: 1; SizeY_mm: 0.5; SizeZ_mm: 0.6; Value2: 0.063W; AEC Qualified: Y; VDC_V: 50V; AEC Category: Q200; AEC Grade: 0
R24 R25 = CMP-0026825-5: RES, 10 k, 5%, 0.063 W, AEC-Q200 Grade 0, 0402; Manufacturer: Vishay-Dale; Power_W: 63mW; TempCo: 200 ppm/C; Value_Code: 10k0; Value: 10k; EIA_Code: E24; SizeX_mm: 1; SizeY_mm: 0.5; SizeZ_mm: 0.6; Value2: 0.063W; AEC Qualified: Y; VDC_V: 50V; AEC Category: Q200; AEC Grade: 0
R26 R31 R402-R404 = CMP-0025697-4: as R405 on sheet HMU
U4 U5 = CMP-0082157-1: High-Immunity, 5.7kVRMS Reinforced Quad-Channel 3/1 Digital Isolator, 100Mbps, DWW0016A (SOIC-16); Alternate Manufacturer: Texas Instruments; SizeAreaWB_mm2: 244.155; SizeZ_mm: 2.65; SizeX_mm: 17.85; SizeY_mm: 10.3; SizeArea_mm2: 183.855; CompType: IC; AEC Qualified: N; AEC Category: Q200
U6 = CMP-0051394-2: Automotive Catalog Single Buffer/Driver With Open-Drain Output, DBV0005A (SOT-23-5); Manufacturer: Texas Instruments; Generic Part Number: SN74LVC1G07-Q1; ICC @ Nom Voltage(Max)(mA): 0.01; VCC(Min)(V): 1.65; 3-State Output: No; Voltage(Nom)(V): 1.8,2.5,3.3,5; Logic: True; Input Type: CMOS/TTL; Bits(#): 1; Output Drive (IOL/IOH)(Max)(mA): 32/-32; Output Type: CMOS; VCC(Max)(V): 5.5; tpd @ Nom Voltage(Max)(ns): 9.8,7,5.7,4.9; F @ Nom Voltage(Max)(Mhz): 150; AEC Category: Q200; AEC Qualified: Y; CompType: IC; SizeAreaWB_mm2: 14.82; SizeArea_mm2: 8.12; SizeX_mm: 2.8; SizeY_mm: 2.9; SizeZ_mm: 1.45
